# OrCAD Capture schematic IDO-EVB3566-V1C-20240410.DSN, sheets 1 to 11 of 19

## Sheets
1 P01. Revision History
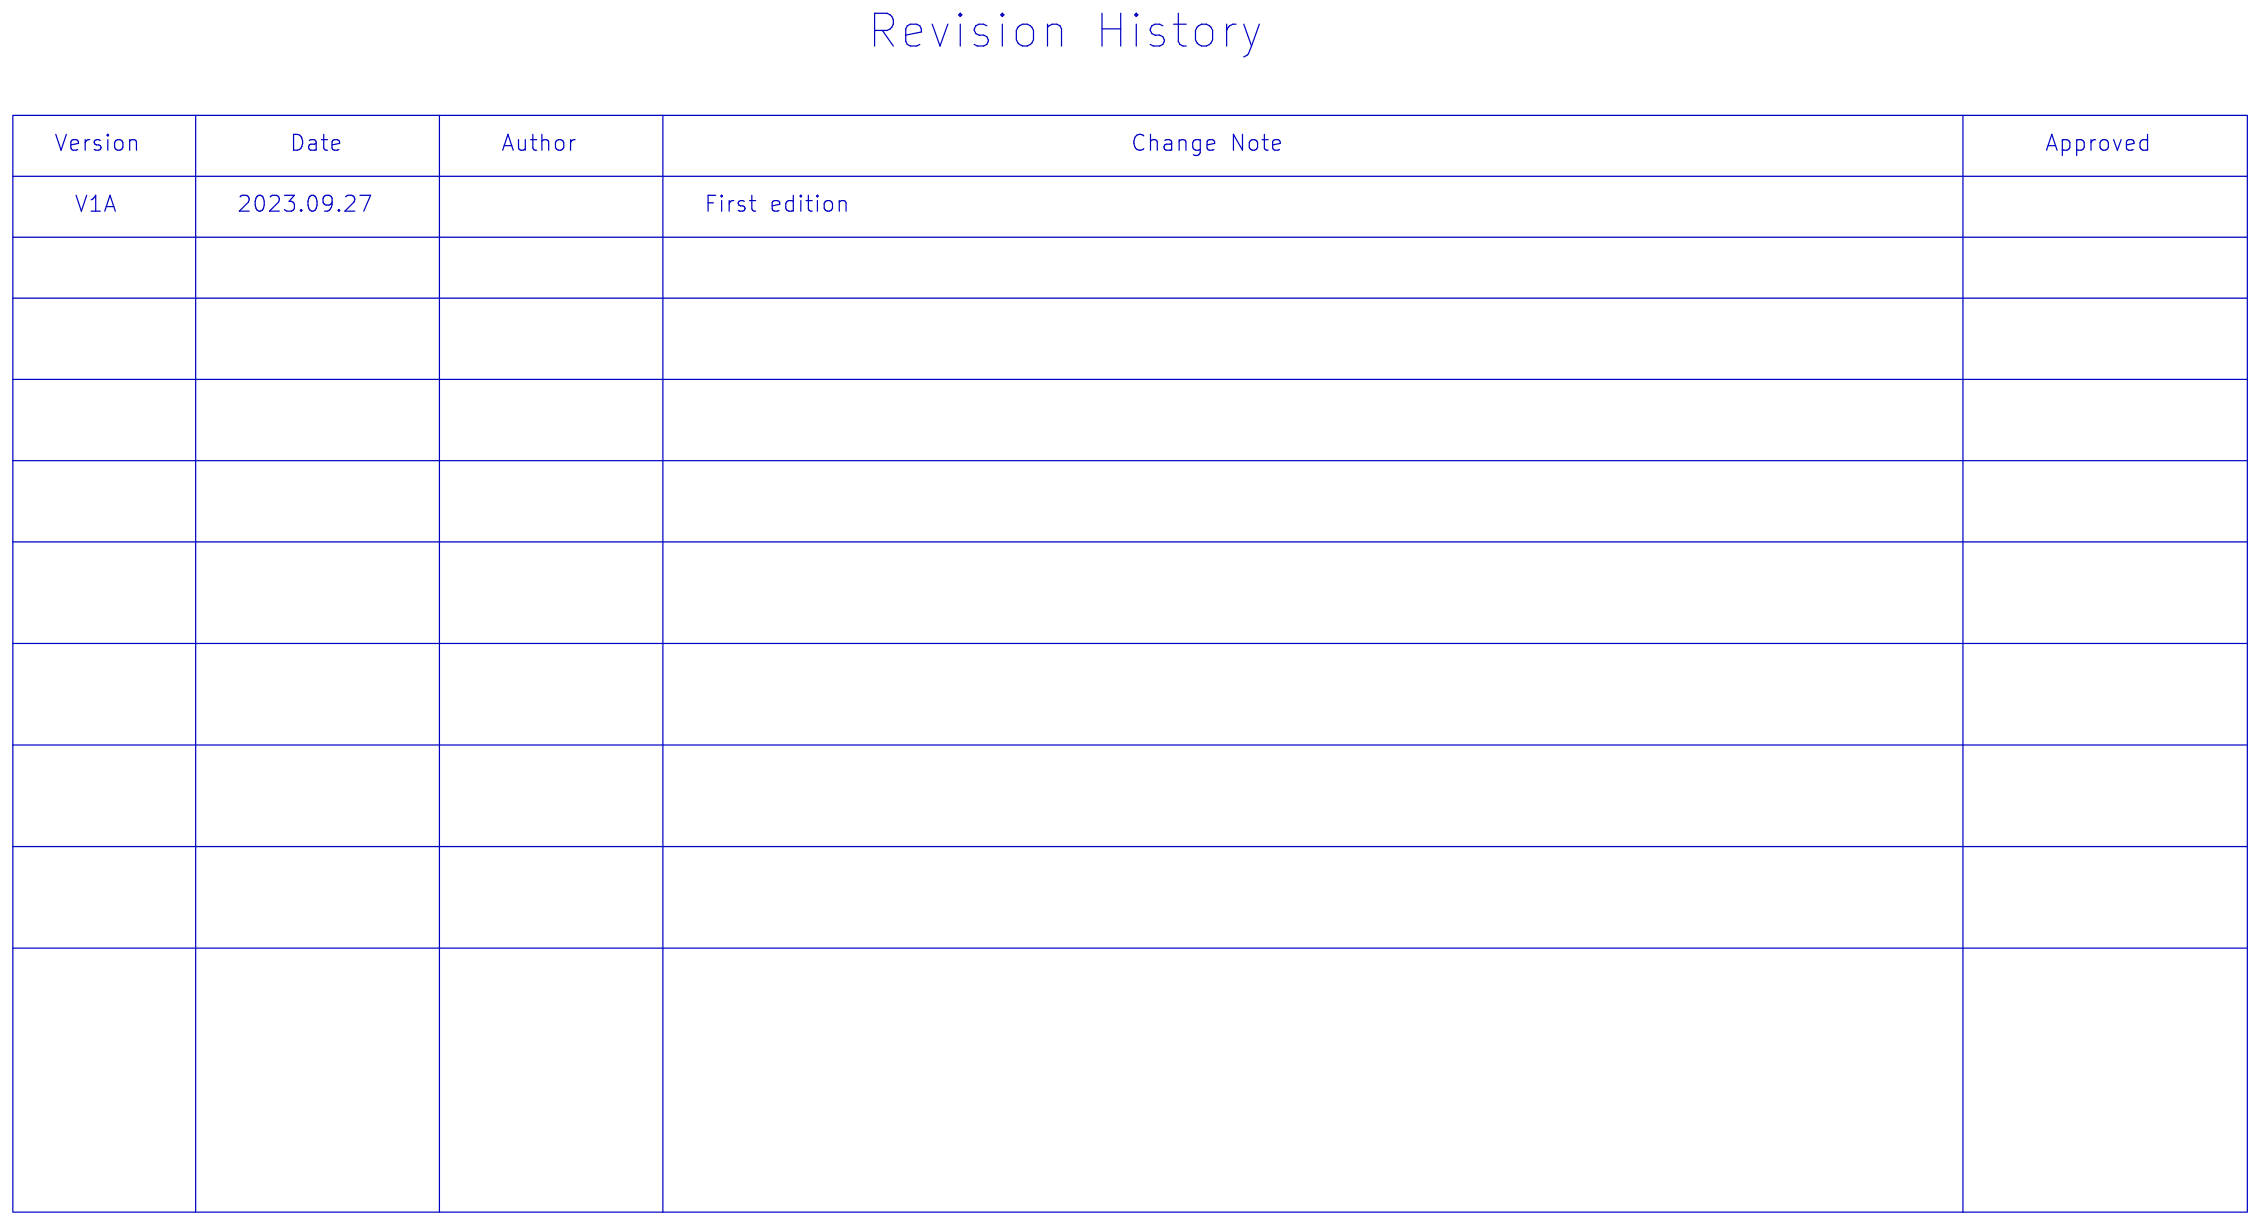
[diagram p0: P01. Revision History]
2 P02. Block_Diagram
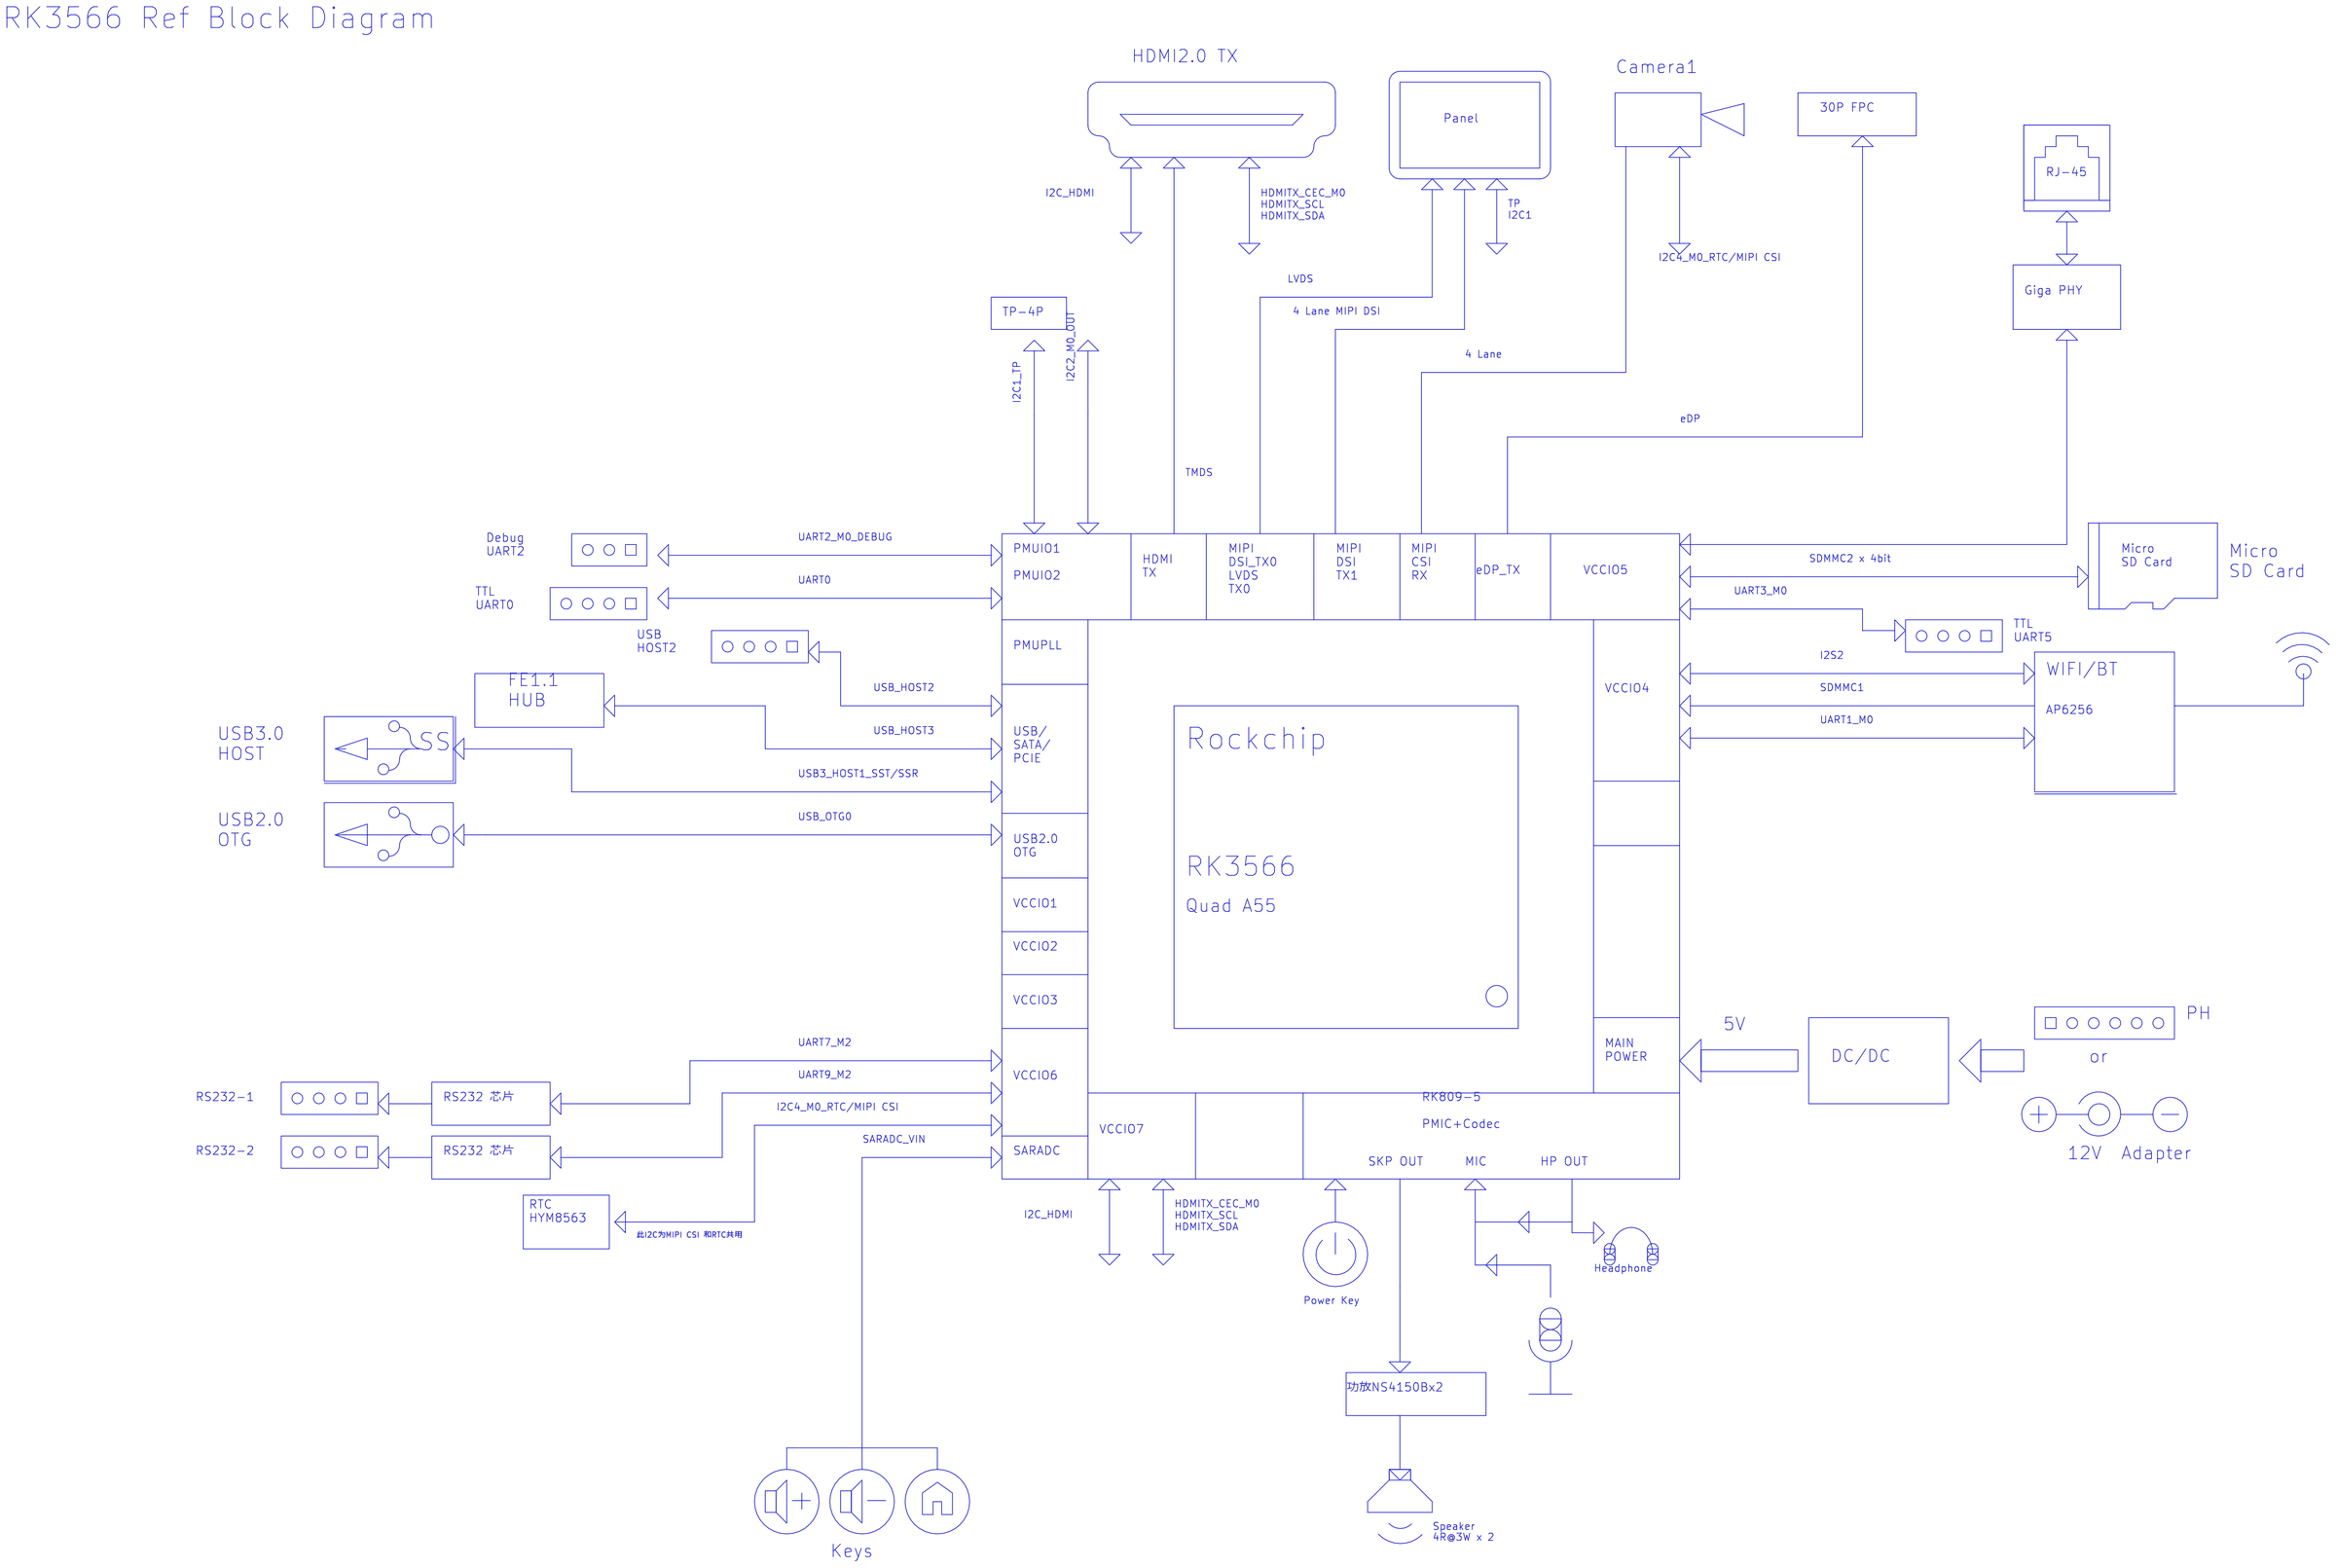
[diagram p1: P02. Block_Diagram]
3 P03. Power Diagram: title: IDO-EVB3568-V2; note: Power Diagram
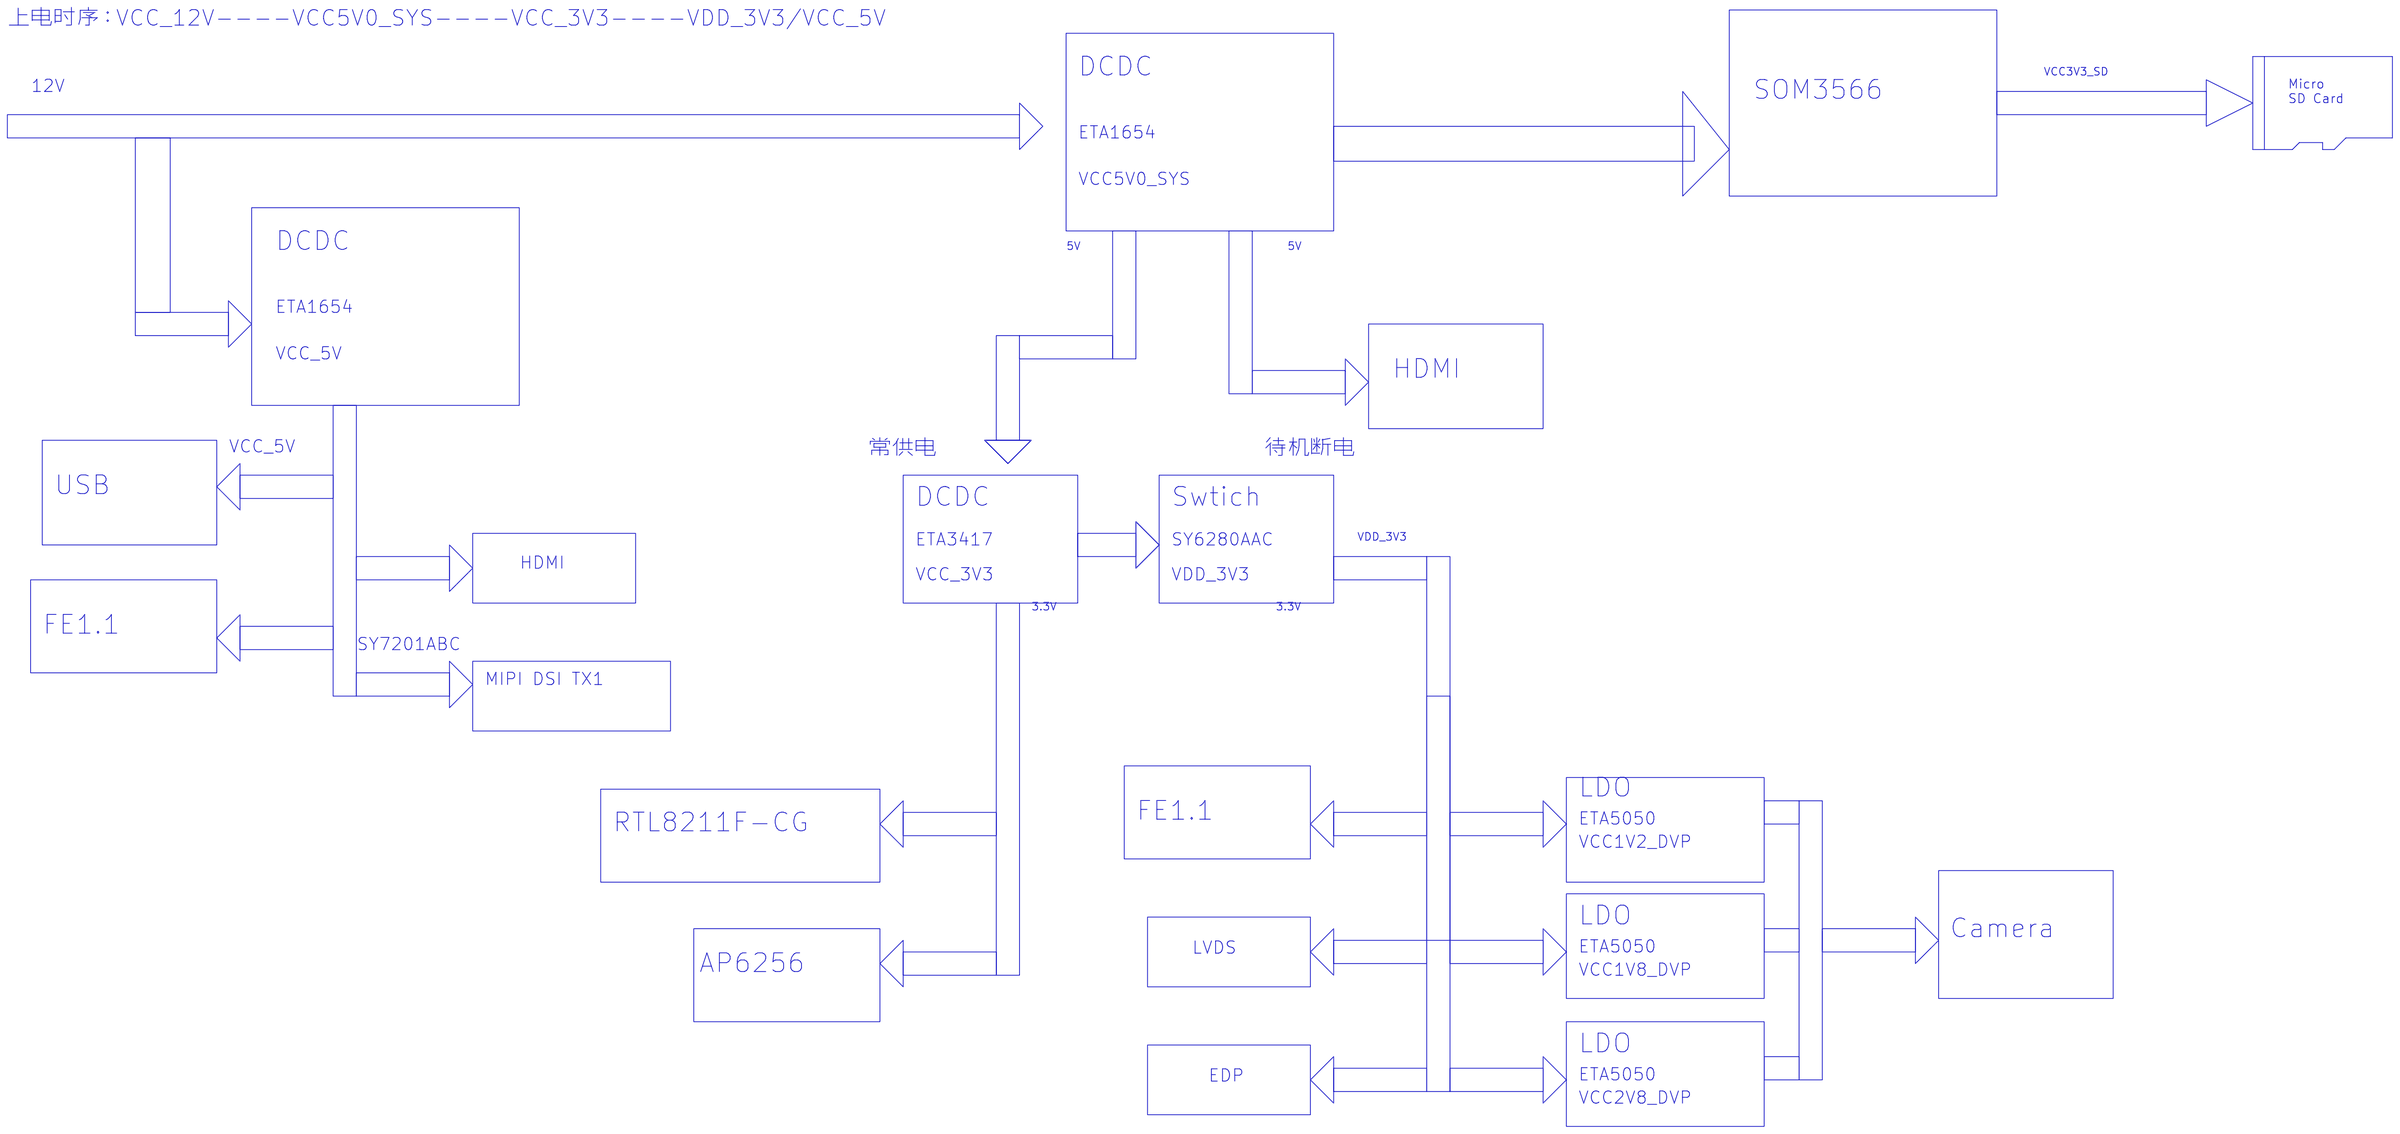
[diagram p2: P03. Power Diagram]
4 P05. SOM3566: size A2
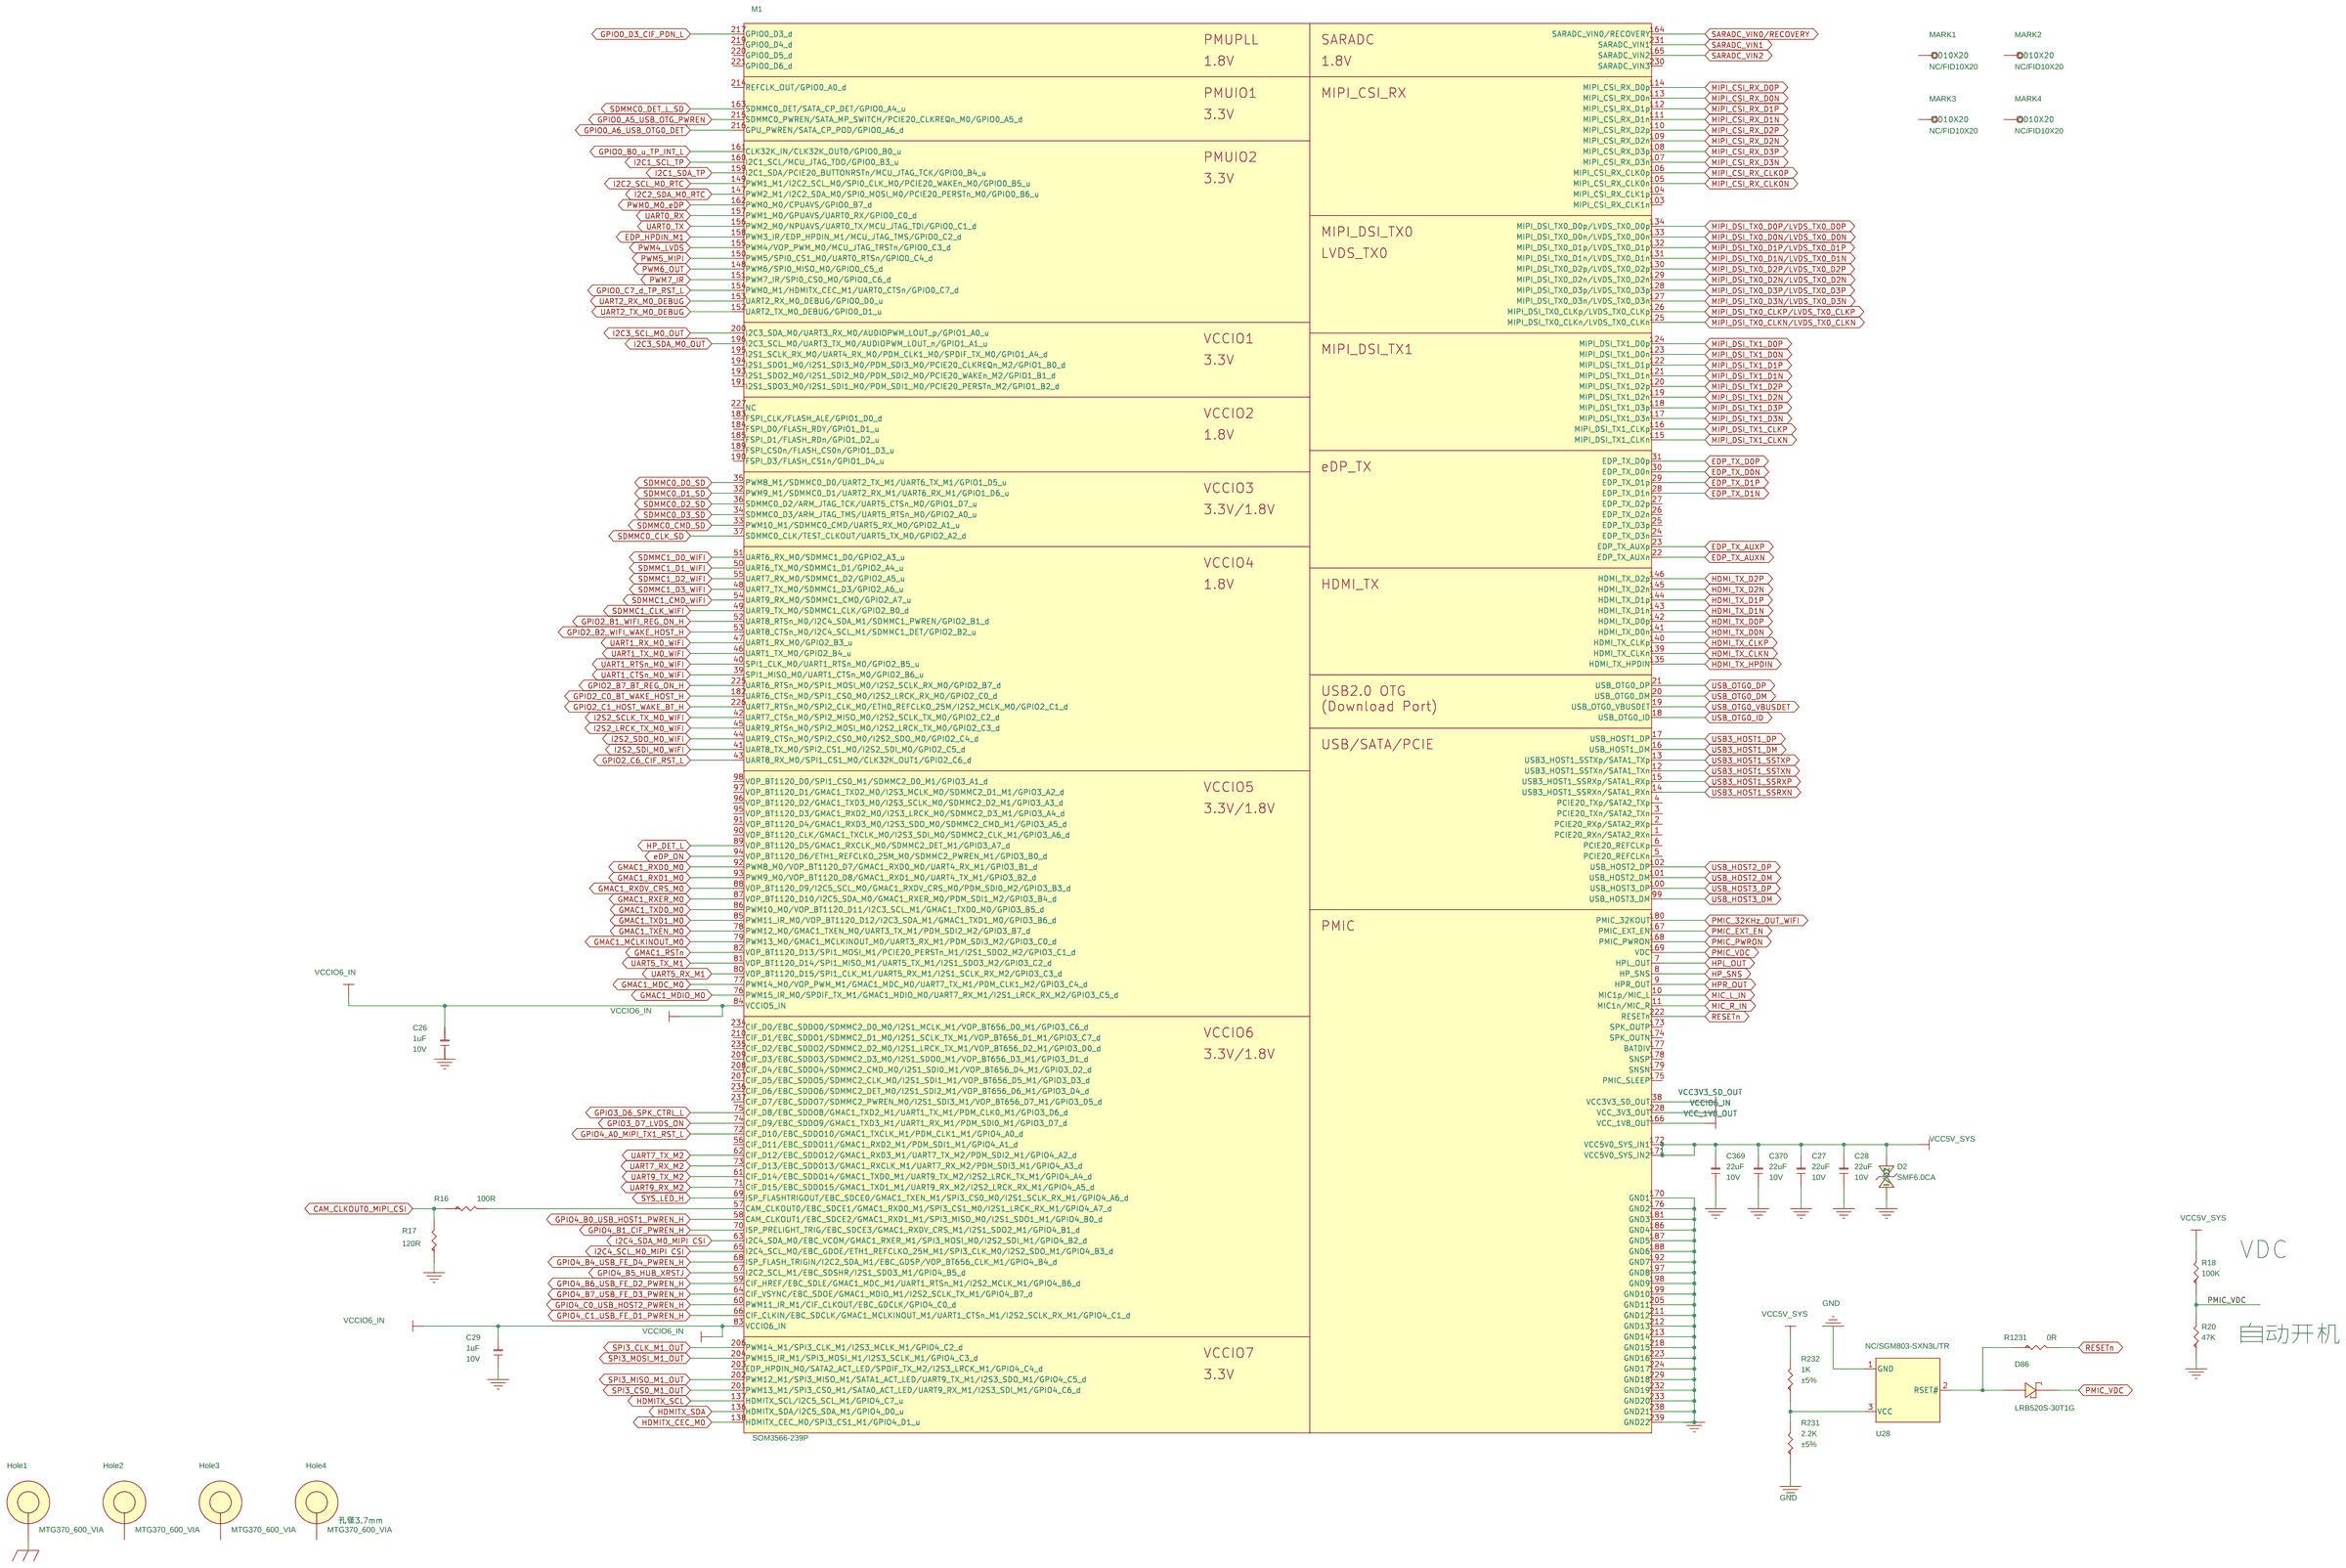
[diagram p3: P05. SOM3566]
5 P07. VO-eDP_TX: size A4; title: IDO-EVB3566-V1; note: VO-eDP Panel
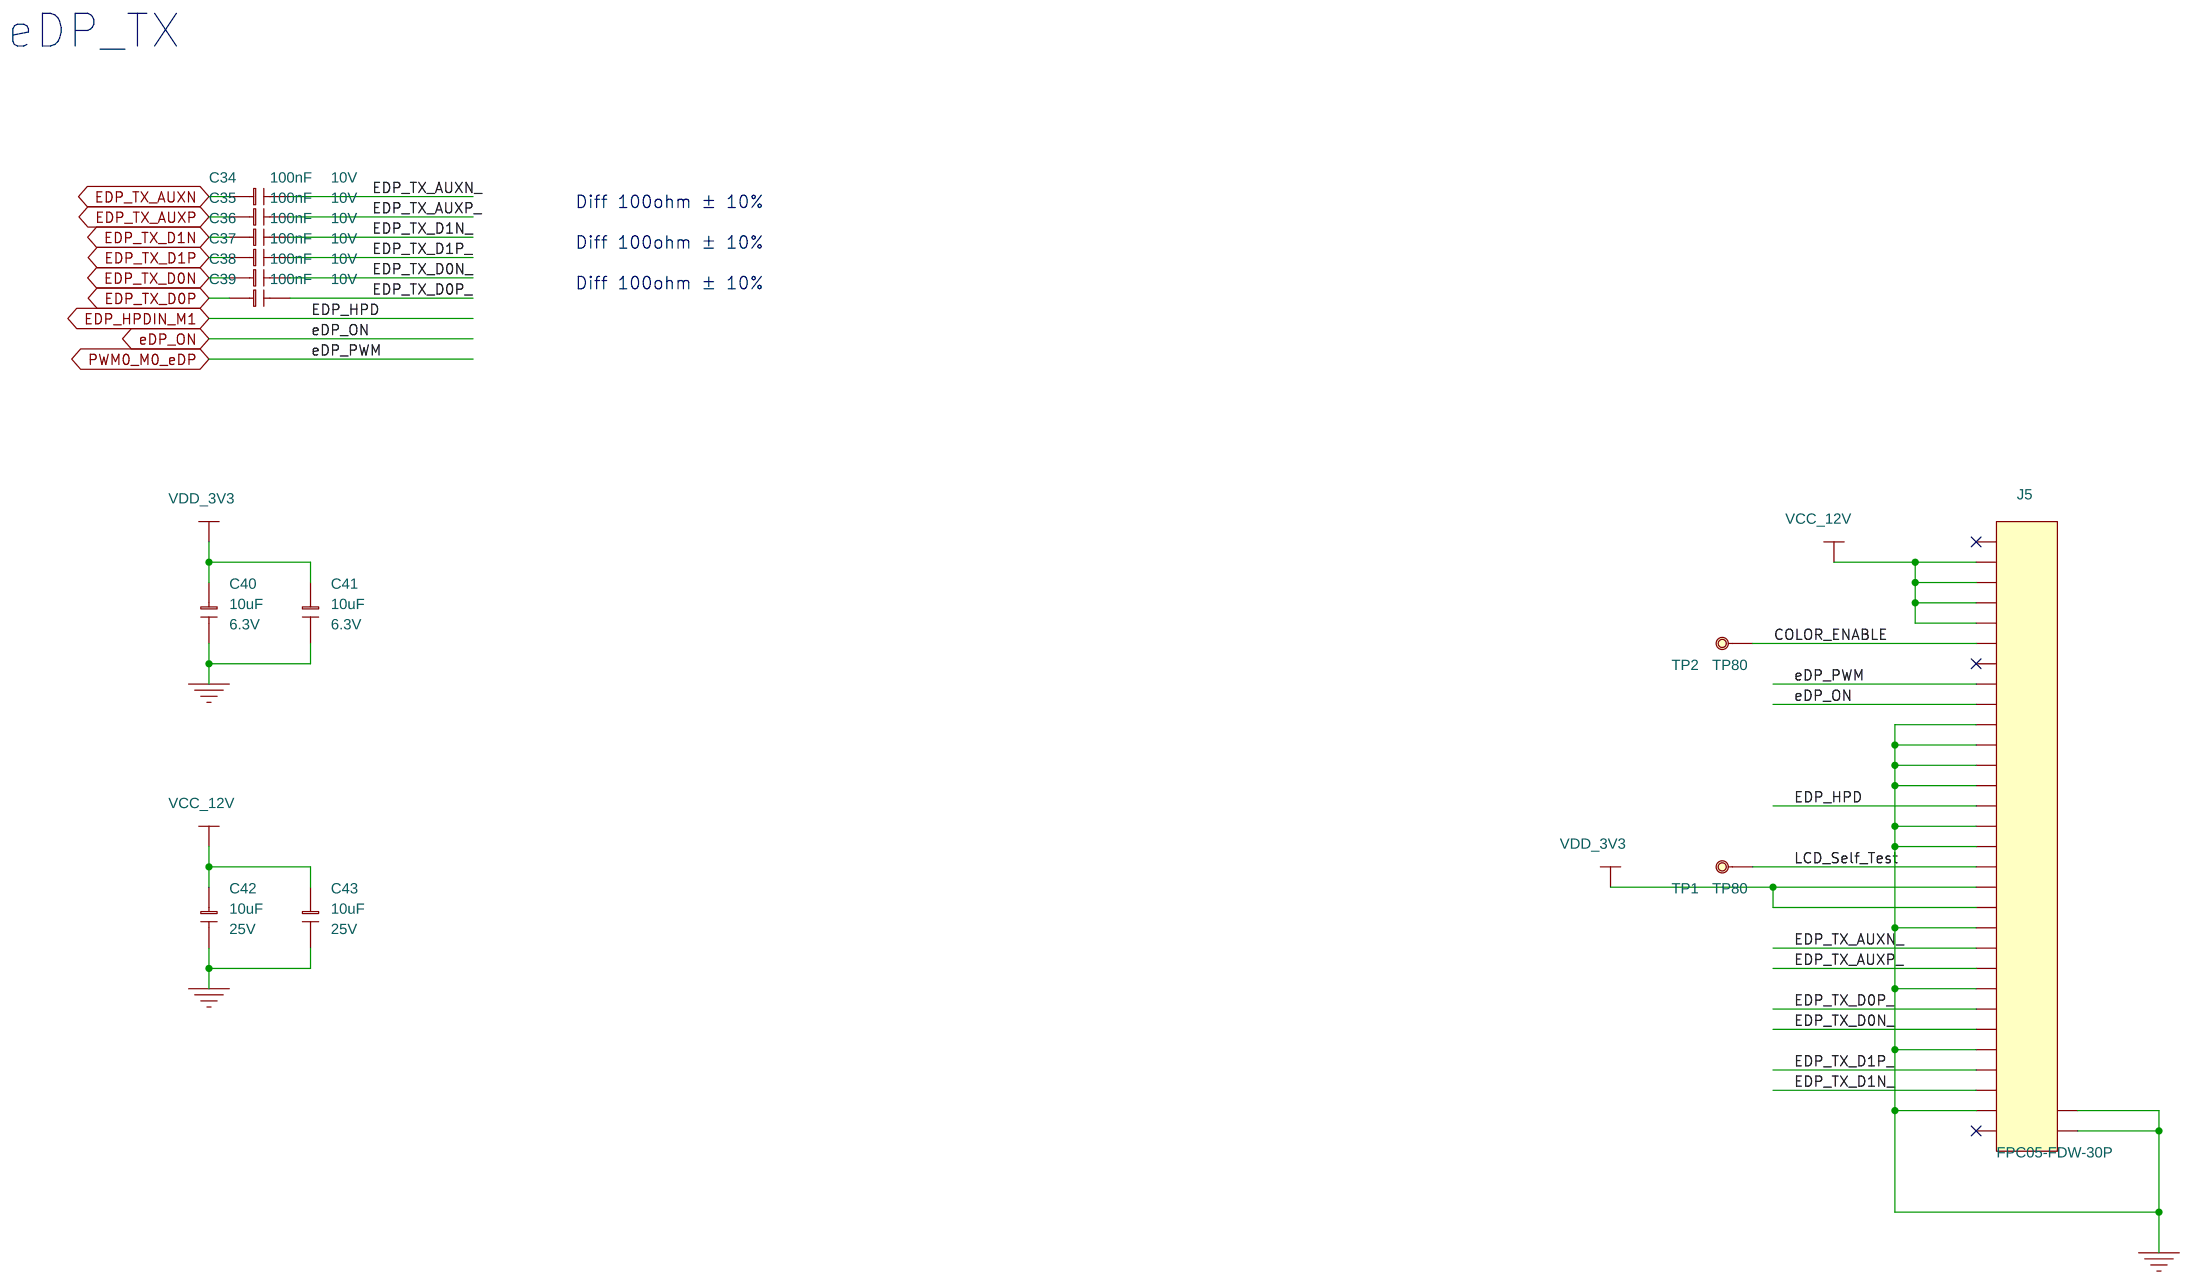
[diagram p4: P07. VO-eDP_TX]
6 P08. VO-HDMI2.0_TX: size A4
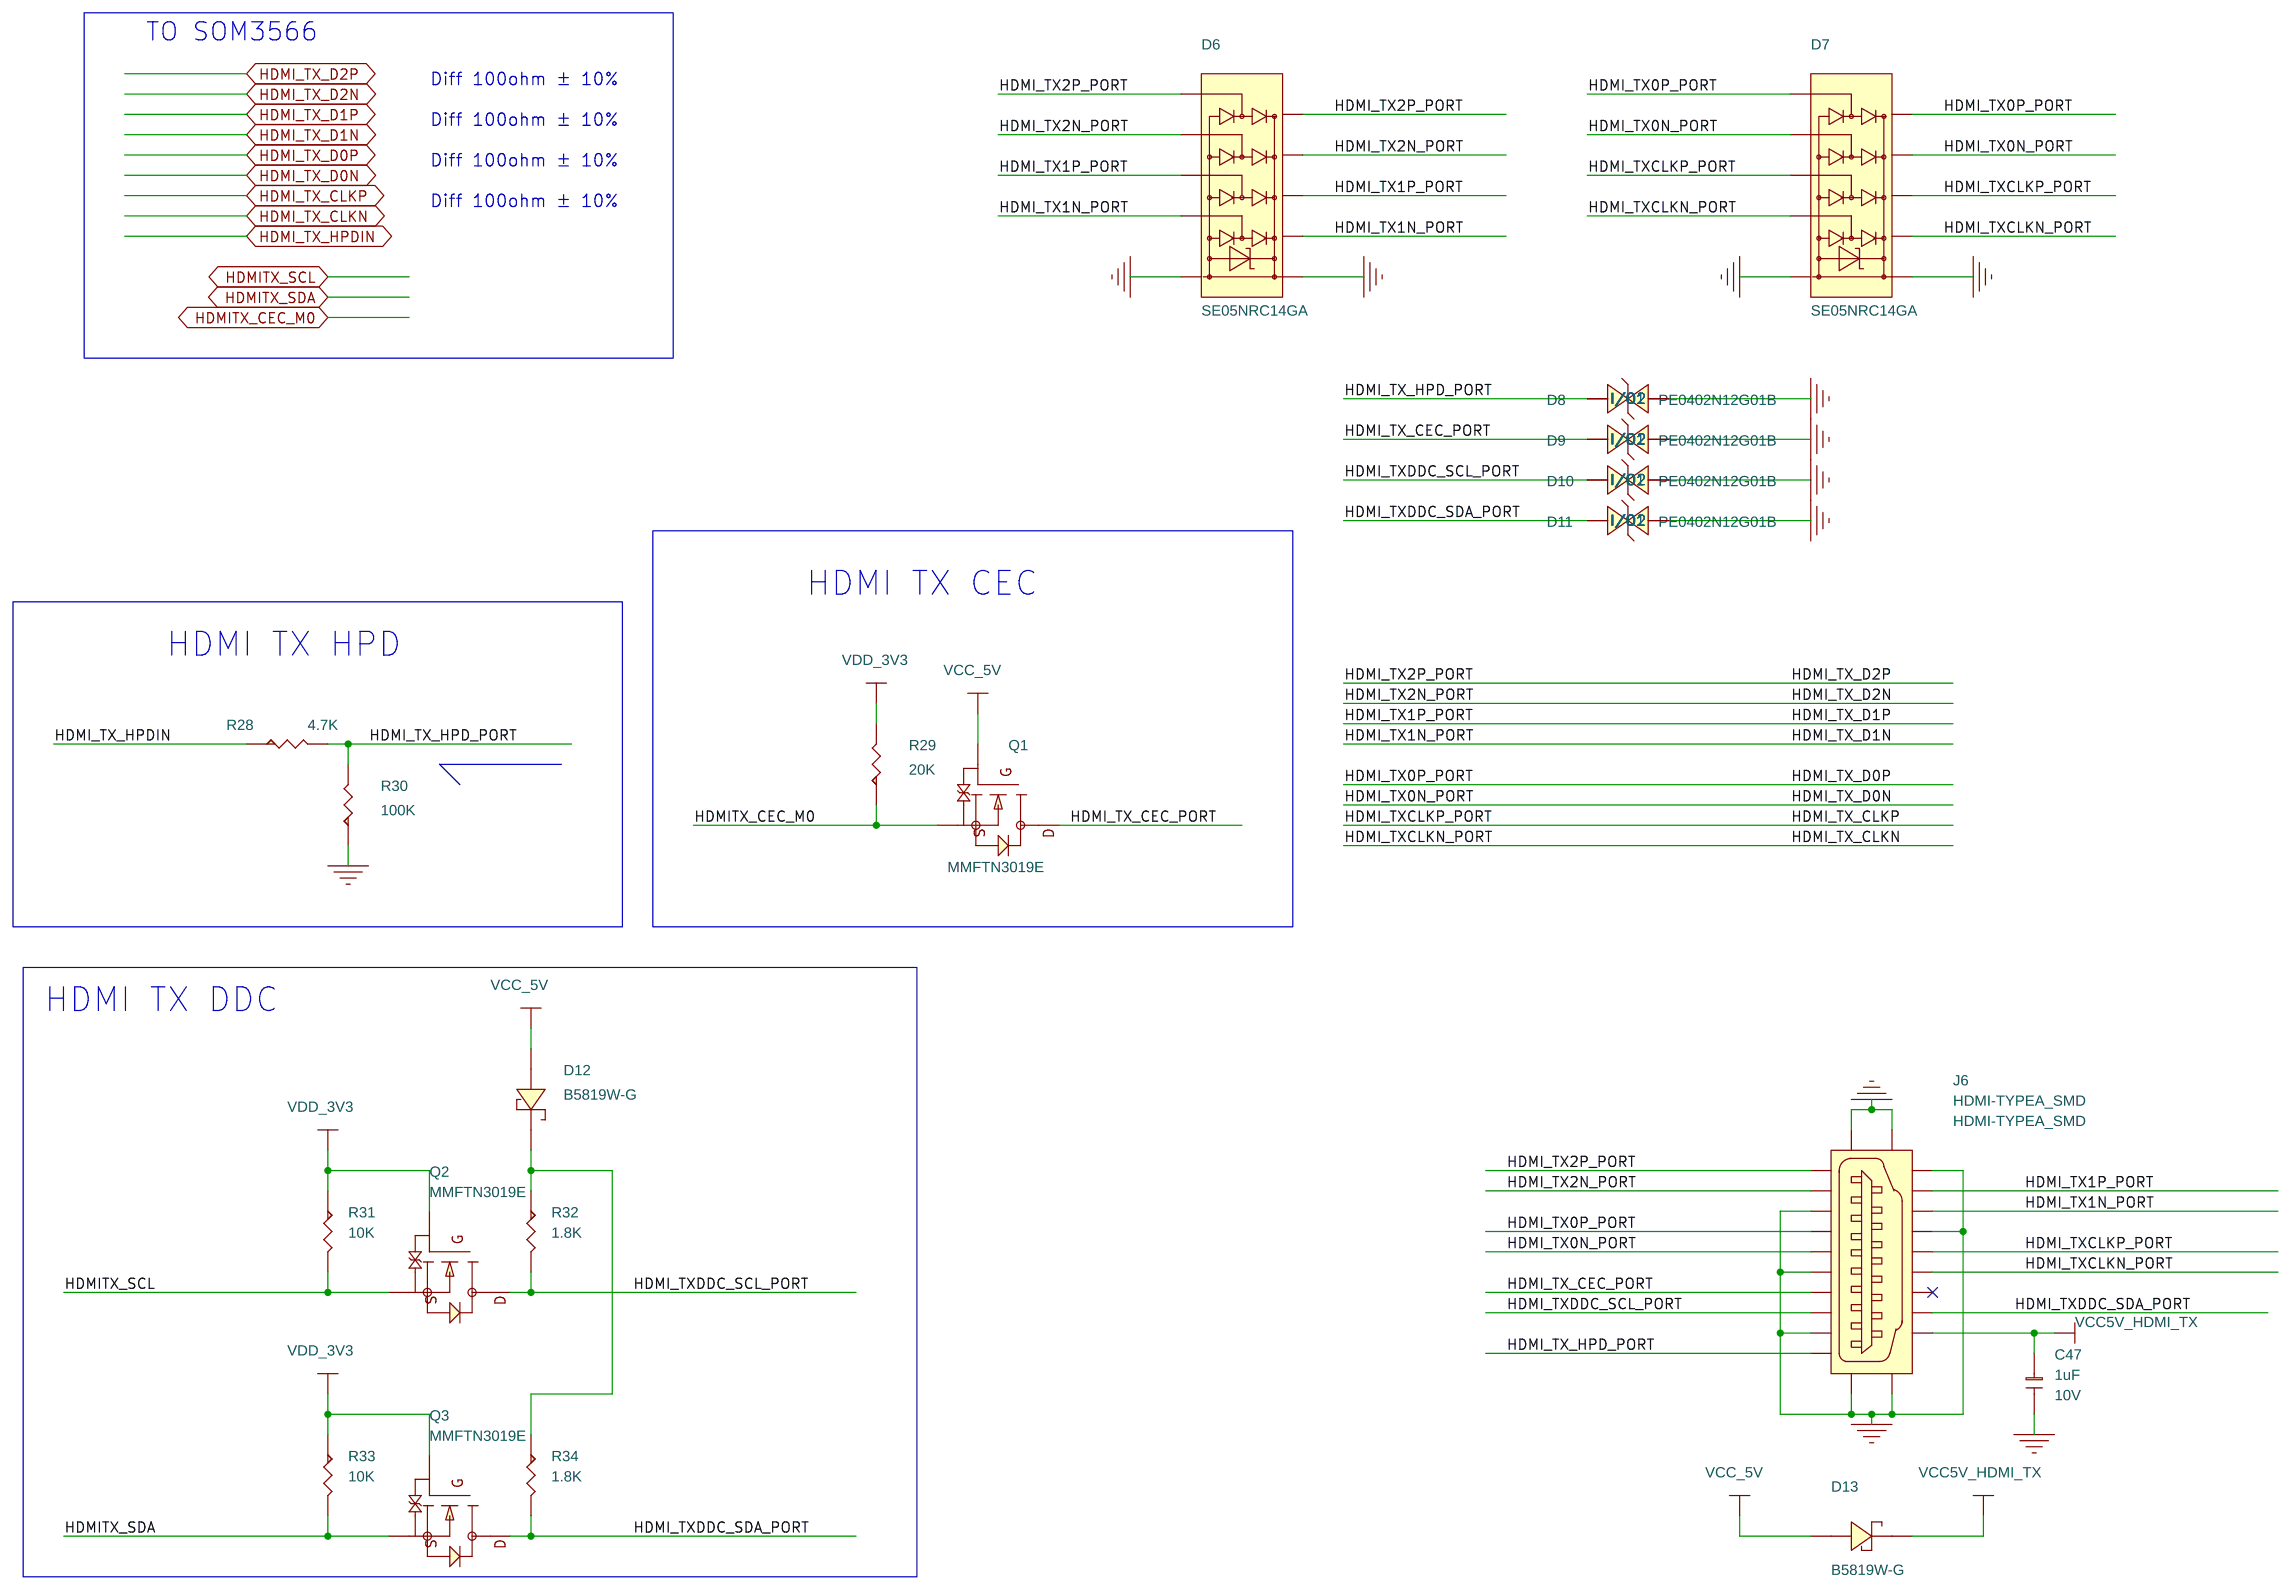
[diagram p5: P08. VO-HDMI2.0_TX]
7 P09. VO-LVDS: size A4
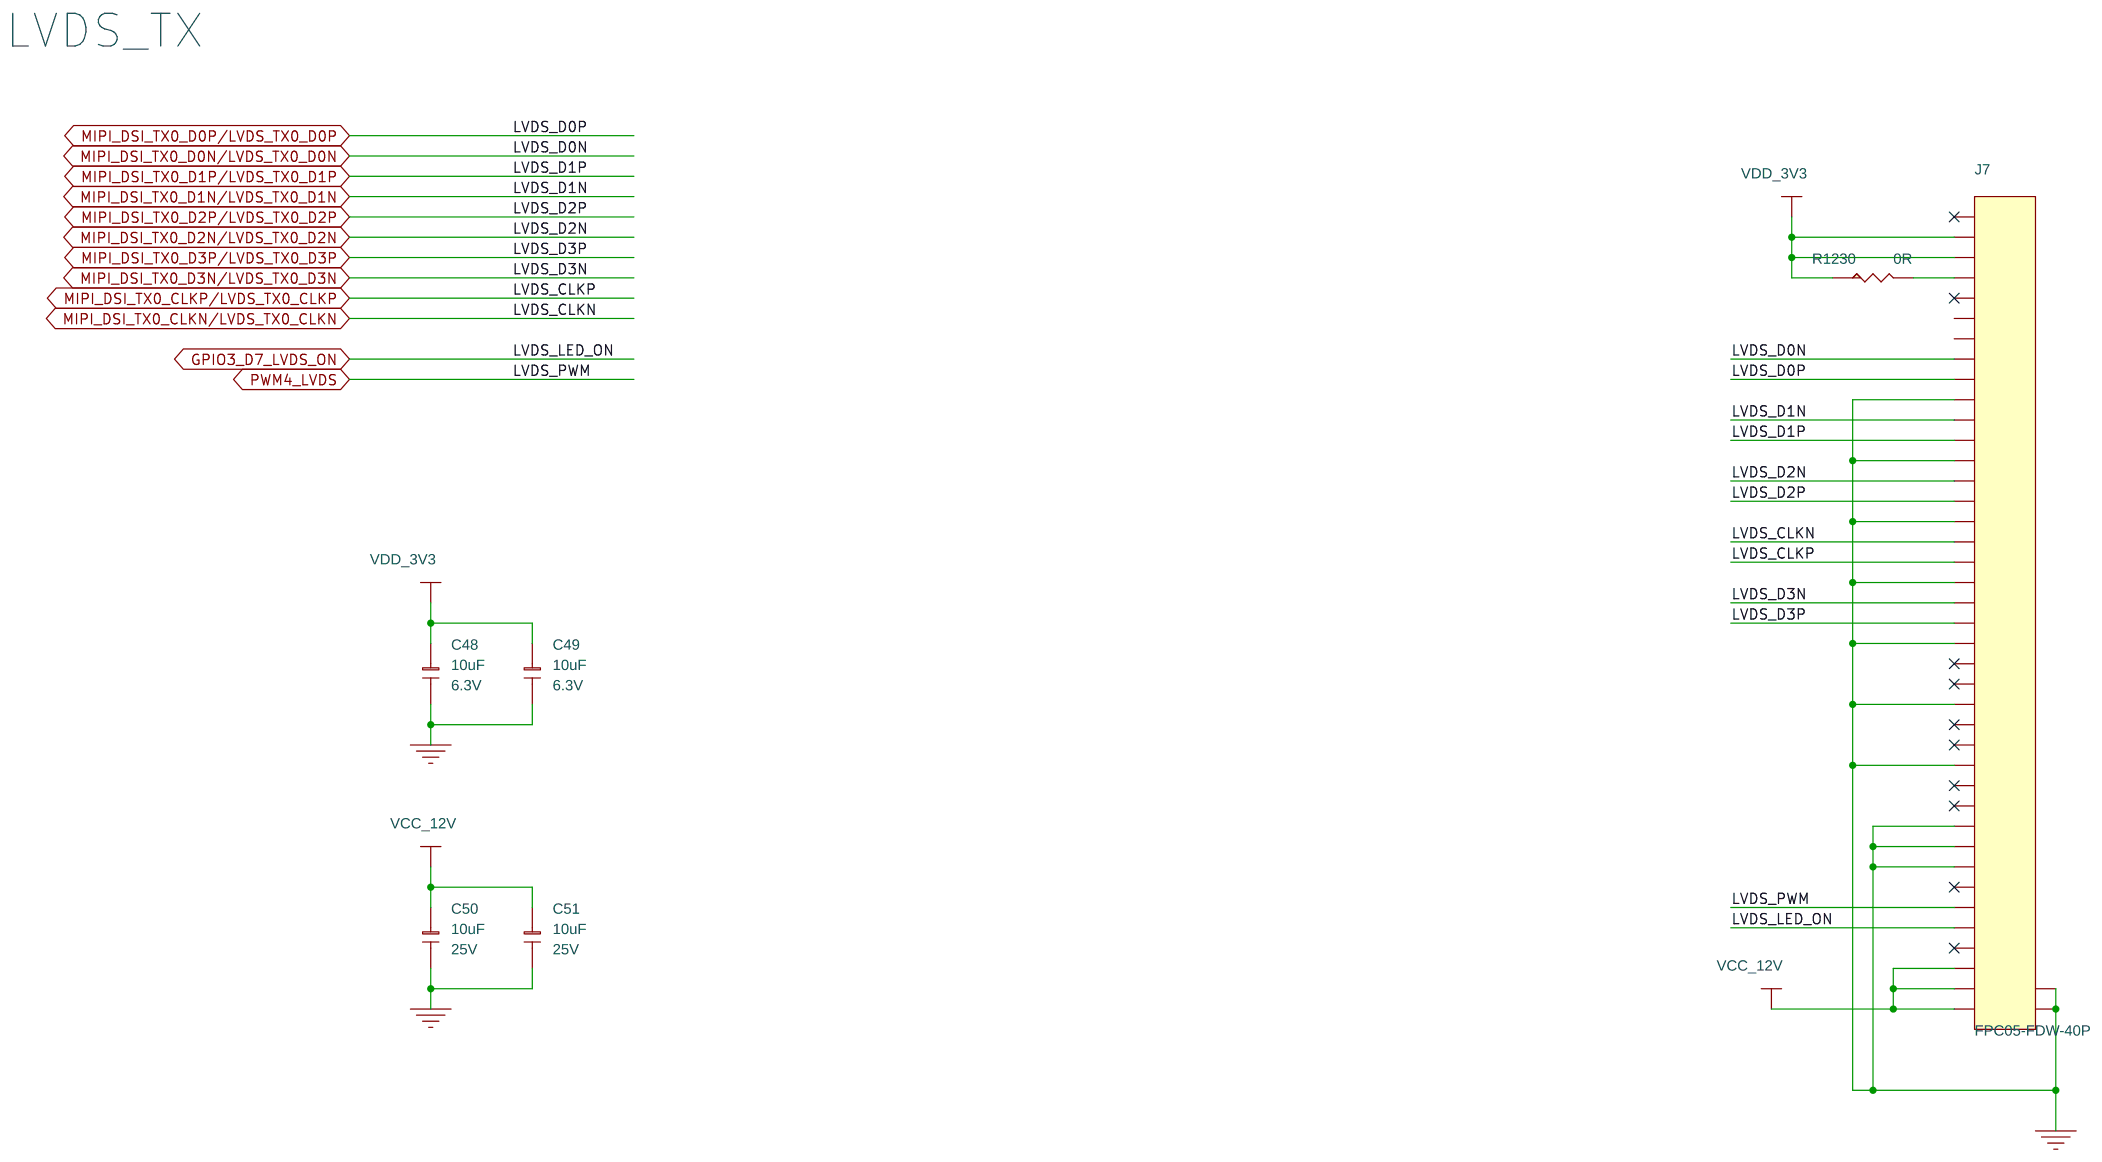
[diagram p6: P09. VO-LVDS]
8 P11. VI-Camera_MIPI_CSI: size A4
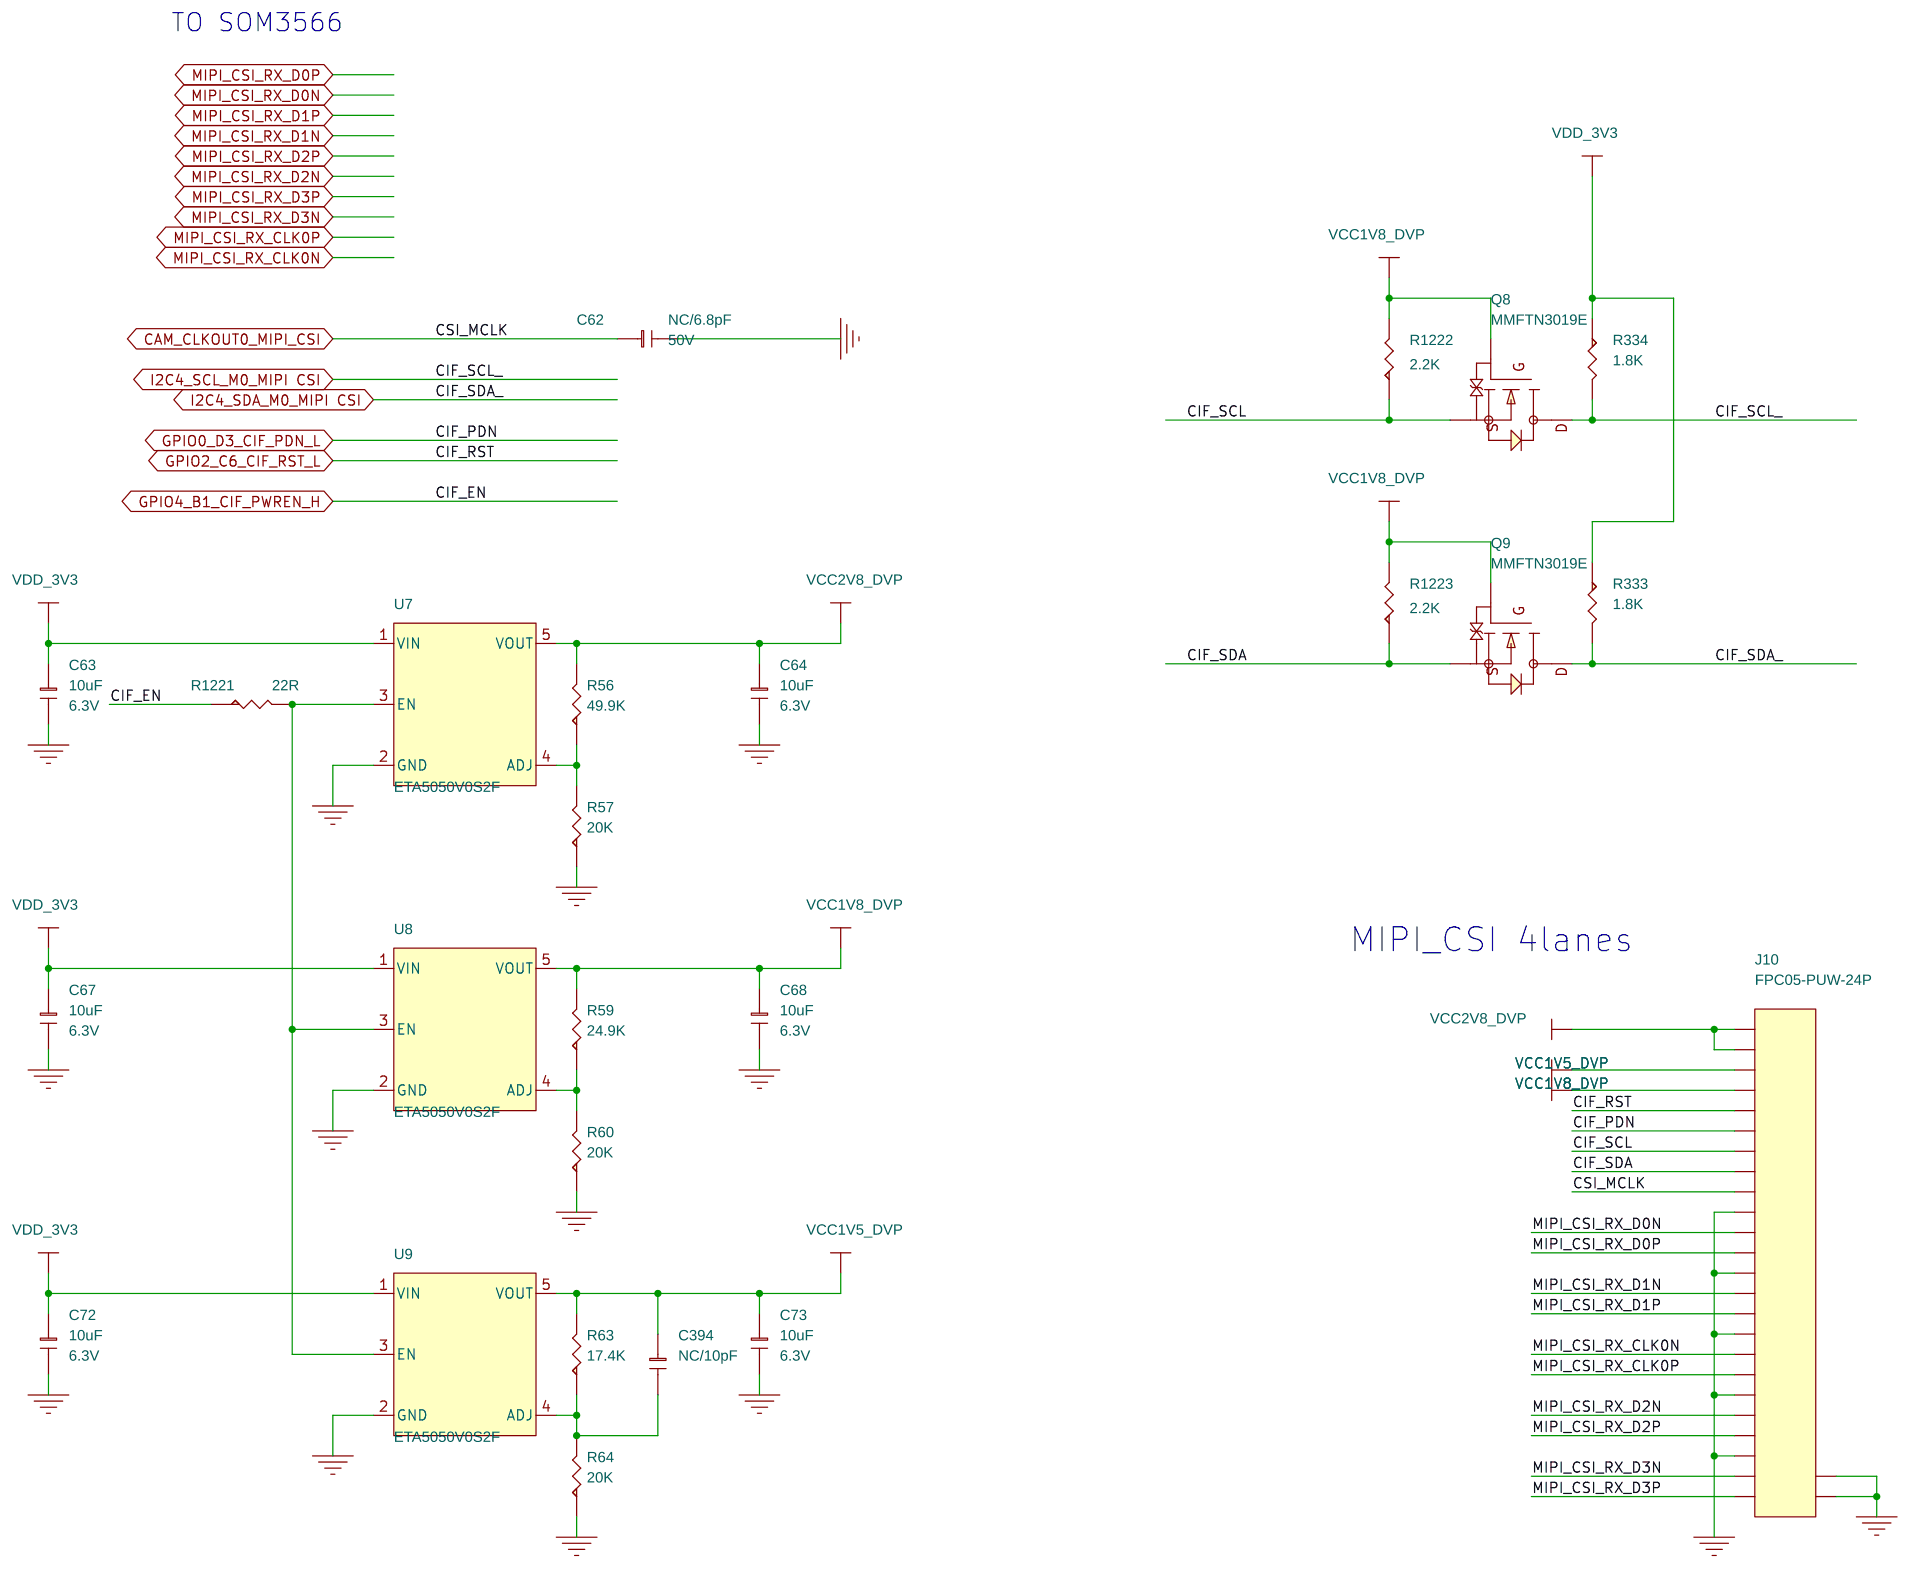
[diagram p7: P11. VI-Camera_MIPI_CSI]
9 P19. GPIO: size A
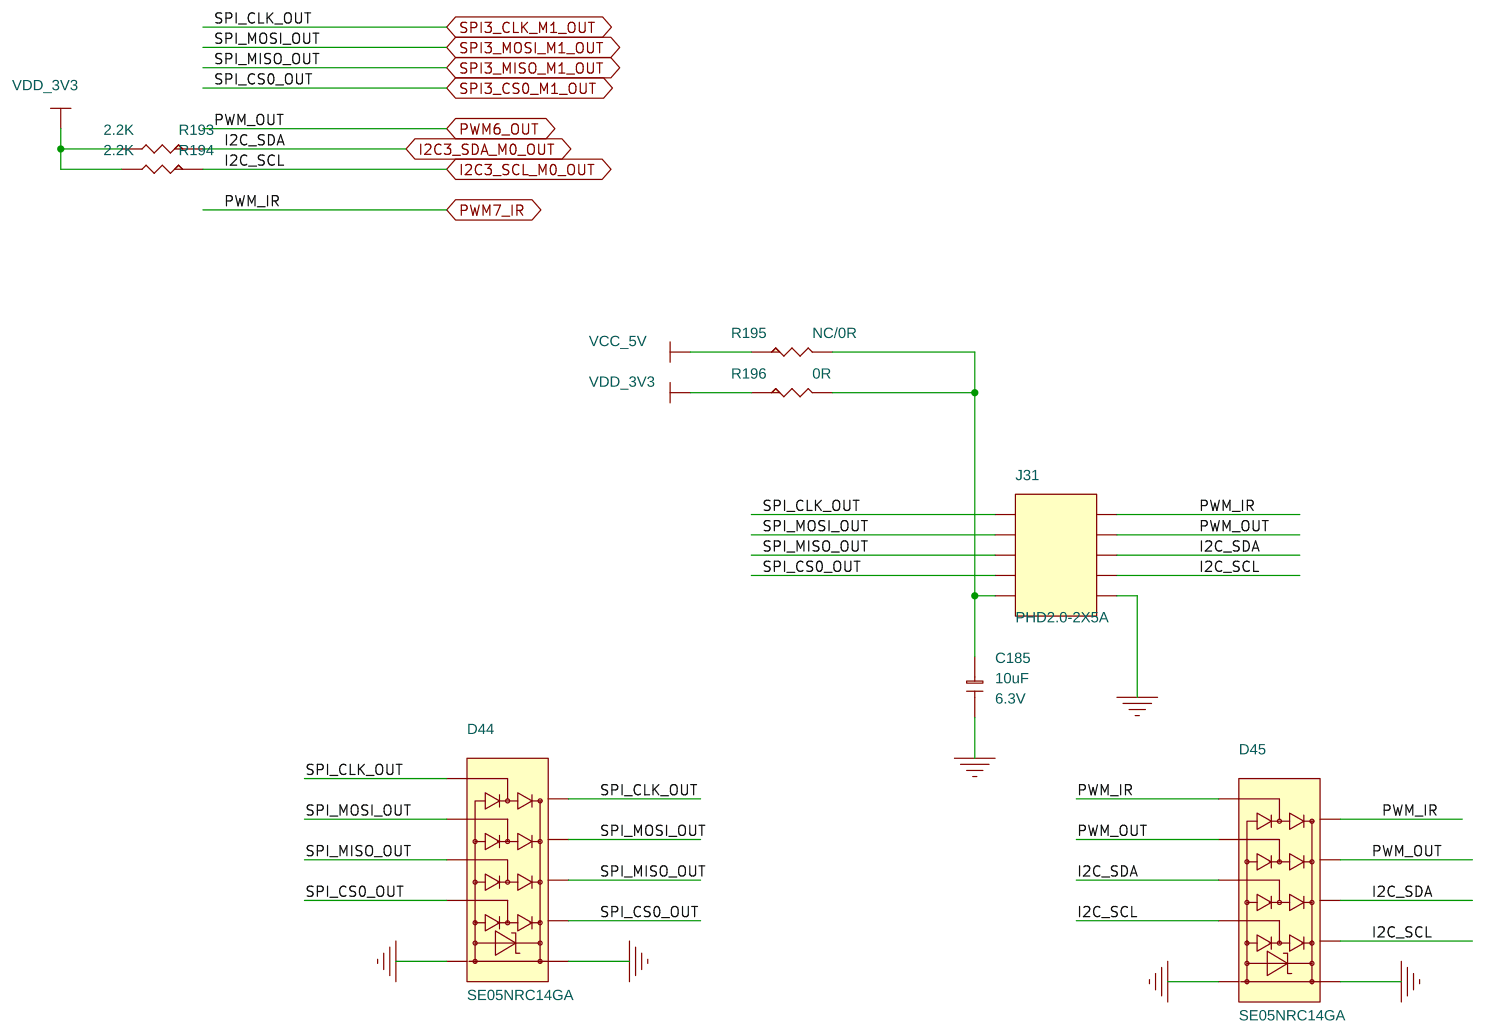
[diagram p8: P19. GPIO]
10 P17. 1MIC/2SPK/HP: size A4
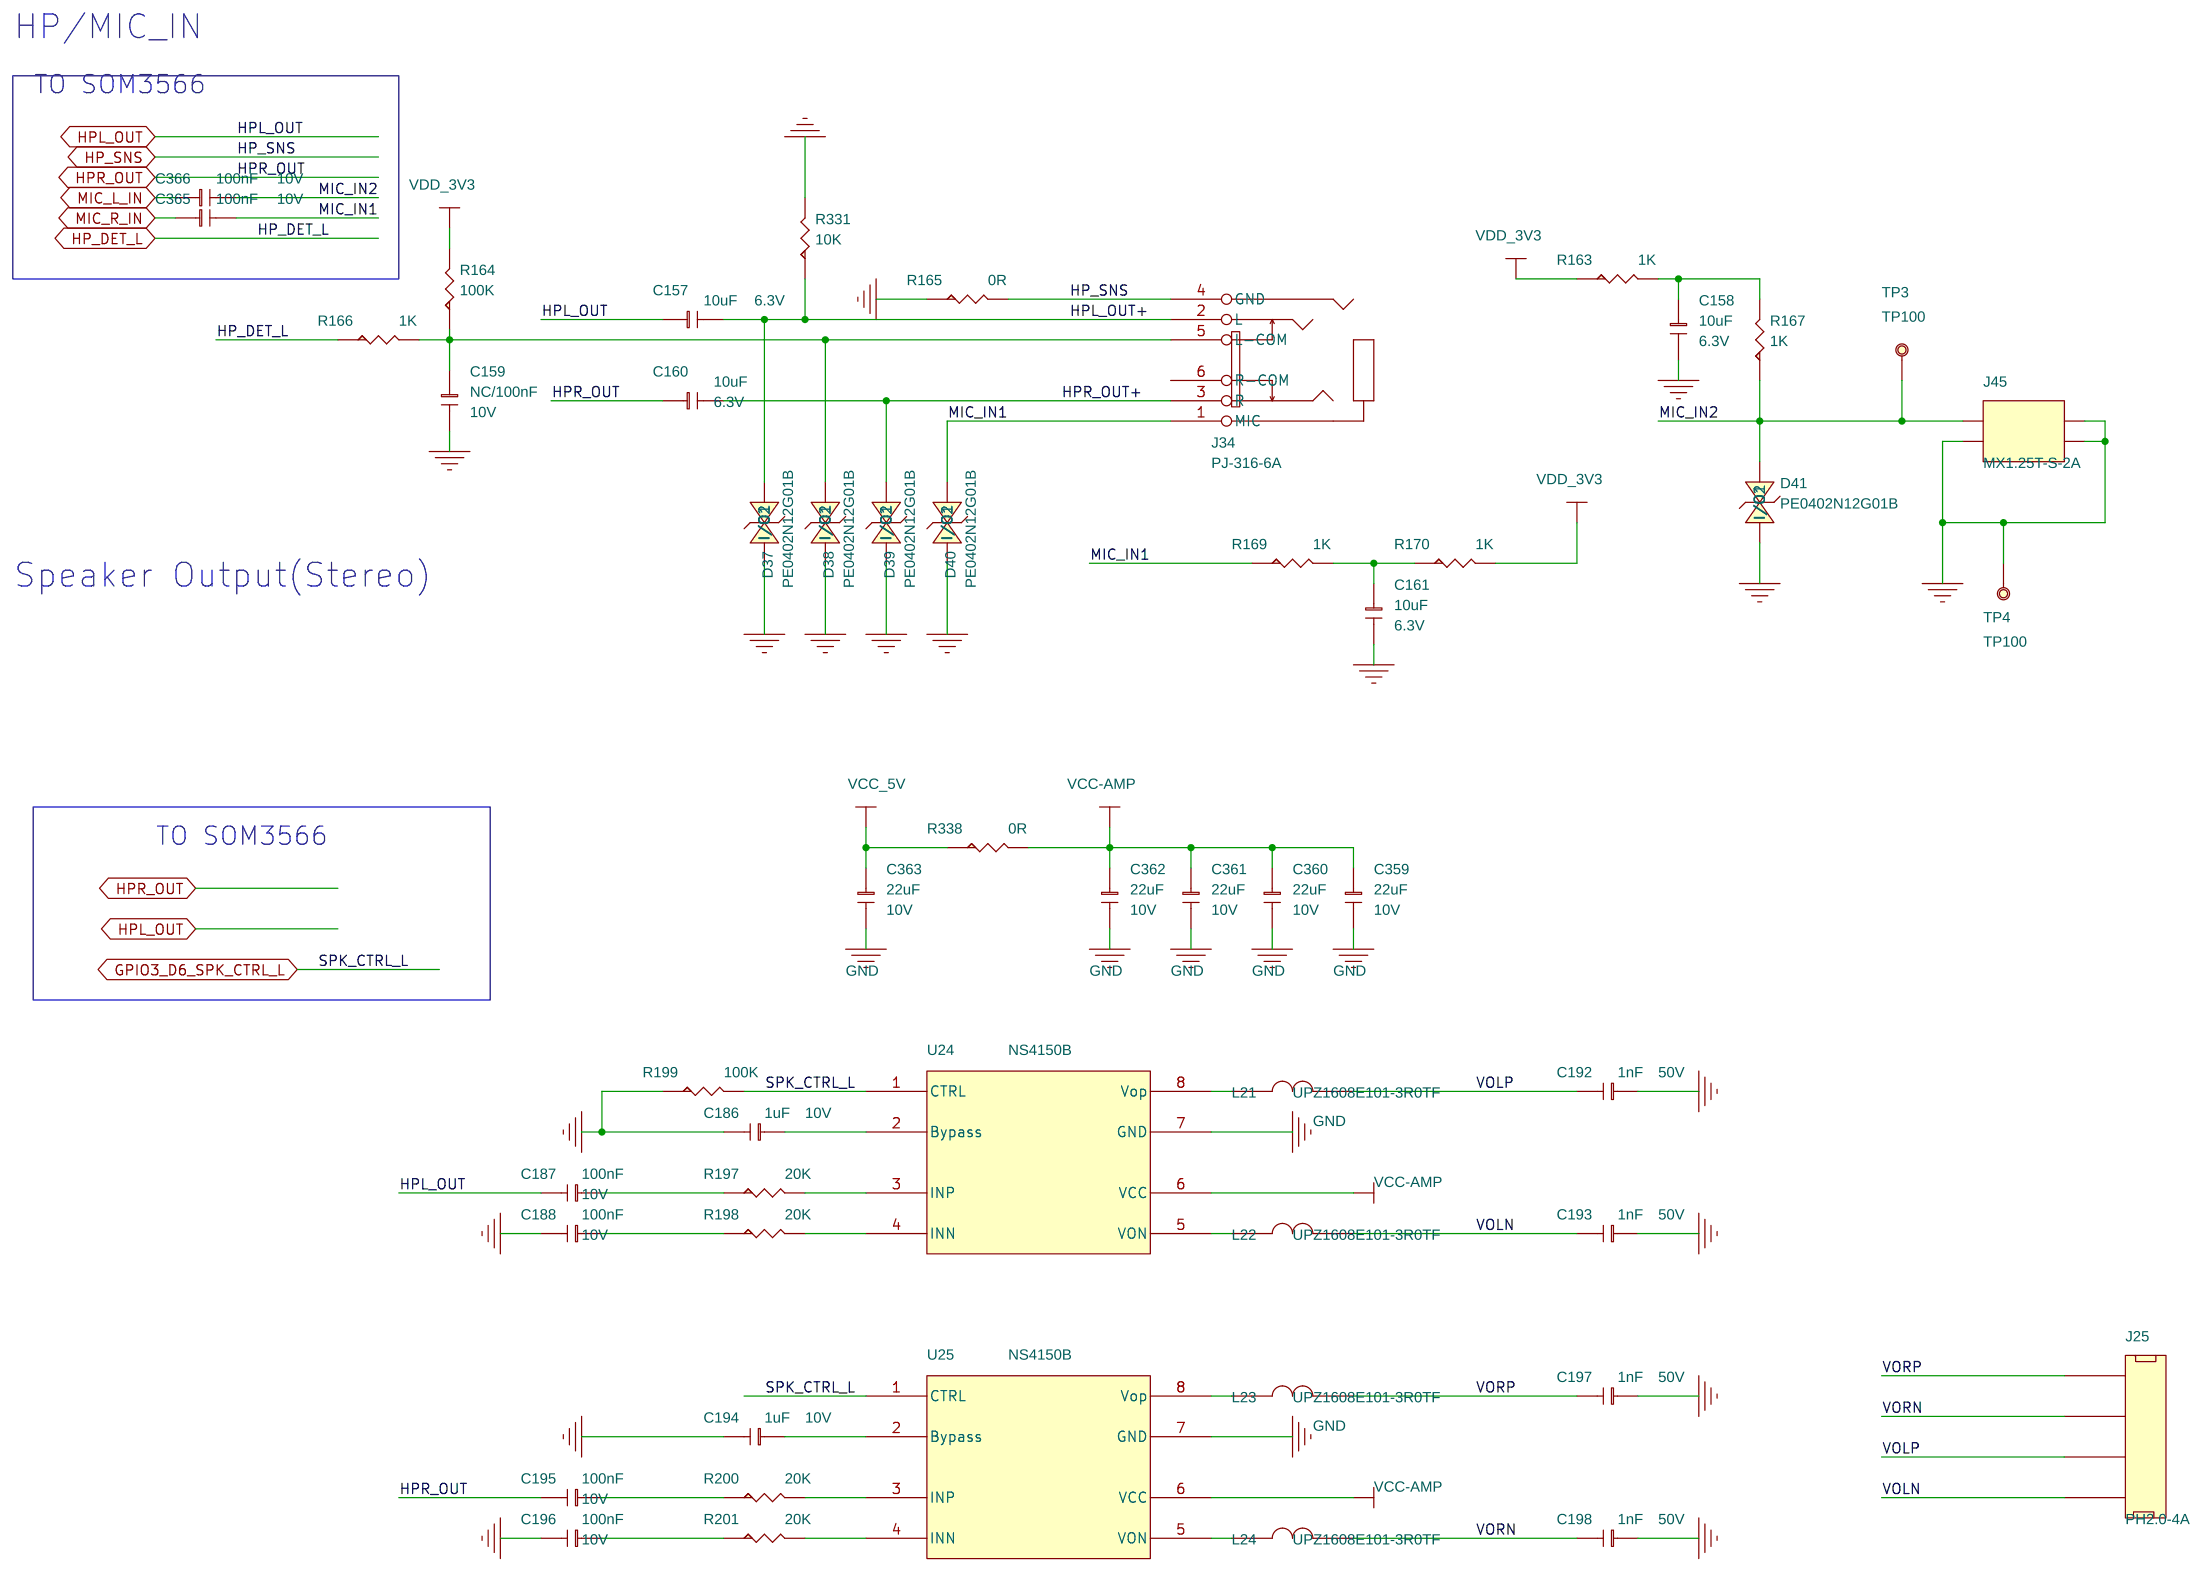
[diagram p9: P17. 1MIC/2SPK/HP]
11 P04. Power/LED: size A4
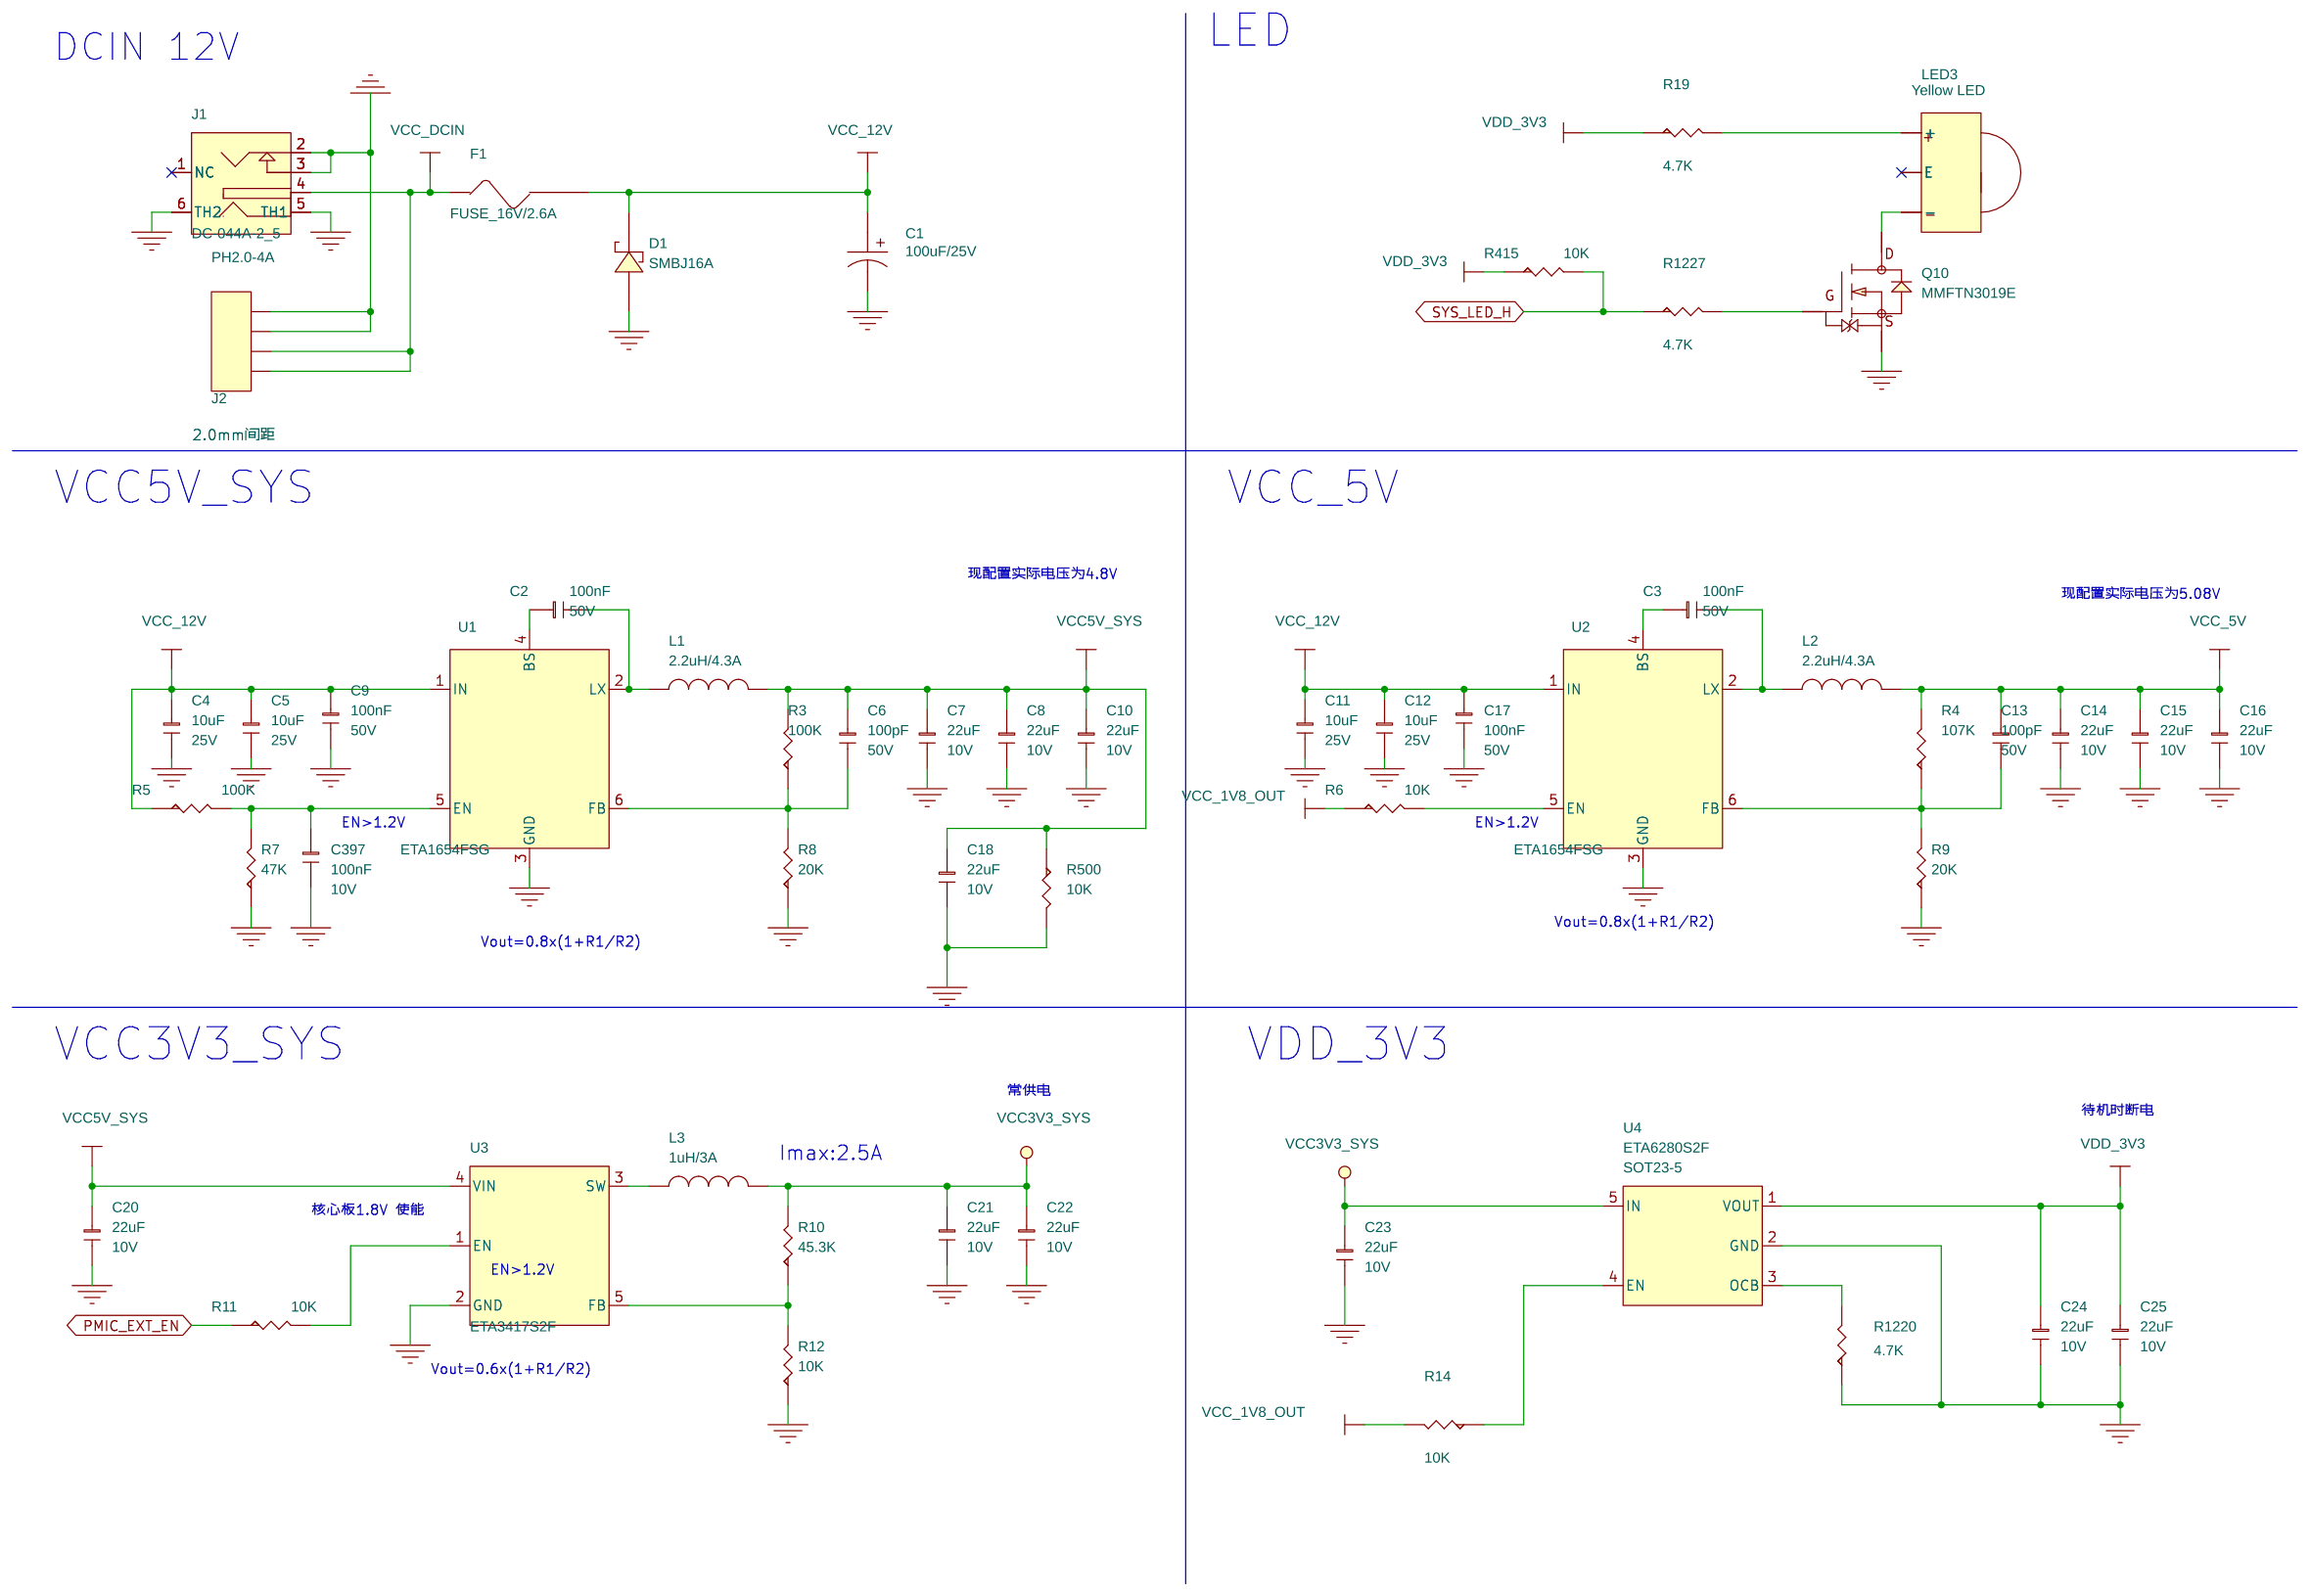
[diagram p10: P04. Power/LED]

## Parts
sheet P04. Power/LED
C1  100uF/25V  [CAPAE660X540]
C2  100nF  [C0402]
C3  100nF  [C0402]
C4  10uF  [C0805]
C5  10uF  [C0805]
C6  100pF  [C0402]
C7  22uF  [C0603]
C8  22uF  [C0603]
C9  100nF  [C0402]
C10  22uF  [C0603]
C11  10uF  [C0805]
C12  10uF  [C0805]
C13  100pF  [C0402]
C14  22uF  [C0603]
C15  22uF  [C0603]
C16  22uF  [C0603]
C17  100nF  [C0402]
C18  22uF  [C0603]
C20  22uF  [C0603]
C21  22uF  [C0603]
C22  22uF  [C0603]
C23  22uF  [C0603]
C24  22uF  [C0603]
C25  22uF  [C0603]
C397  100nF  [C0402]
D1  SMBJ16A  [SMB_DO-214AA]
F1  FUSE_16V/2.6A  [SMD1812]
J1  DC-044A-2_5  [DC-044A-2_0-DIP]
J2  PH2.0-4A  [PH200-4A]
L1  2.2uH/4.3A  [IND_404020]
L2  2.2uH/4.3A  [IND_404020]
L3  1uH/3A  [IND_252012]
LED3  Yellow LED  [LED-SMD_3_2X1_5X1_0]
Q10  MMFTN3019E  [SOT523]
R3  100K  [R0402]
R4  107K  [R0402]
R5  100K  [R0402]
R6  10K  [R0402]
R7  47K  [R0402]
R8  20K  [R0402]
R9  20K  [R0402]
R10  45.3K  [R0402]
R11  10K  [R0402]
R12  10K  [R0402]
R14  10K  [R0402]
R19  4.7K  [R0402]
R415  10K  [R0402]
R500  10K  [R0402]
R1220  4.7K  [R0402]
R1227  4.7K  [R0402]
U1  ETA1654FSG  [SOT563]
U2  ETA1654FSG  [SOT563]
U3  ETA3417S2F  [SOT23-5]
U4  ETA6280S2F  [SOT23-5]
sheet P05. SOM3566
C26  1uF  [C0402]
C27  22uF  [C0603]
C28  22uF  [C0603]
C29  1uF  [C0402]
C369  22uF  [C0603]
C370  22uF  [C0603]
D2  SMF6.0CA  [SOD-123F]
D86  LRB520S-30T1G  [SOD523]
Hole1  MTG370_600_VIA  [MTG370_600_VIA]
Hole2  MTG370_600_VIA  [MTG370_600_VIA]
Hole3  MTG370_600_VIA  [MTG370_600_VIA]
Hole4  MTG370_600_VIA  [MTG370_600_VIA]
M1  SOM3566-239P  [SOM3566-239P]
MARK1  NC/FID10X20  [FID10X20]
MARK2  NC/FID10X20  [FID10X20]
MARK3  NC/FID10X20  [FID10X20]
MARK4  NC/FID10X20  [FID10X20]
R16  100R  [R0402]
R17  120R  [R0402]
R18  100K  [R0402]
R20  47K  [R0402]
R231  2.2K  [R0402]
R232  1K  [R0402]
R1231  0R  [R0402]
U28  NC/SGM803-SXN3L/TR  [SOT23]
sheet P07. VO-eDP_TX
C34  100nF  [C0402]
C35  100nF  [C0402]
C36  100nF  [C0402]
C37  100nF  [C0402]
C38  100nF  [C0402]
C39  100nF  [C0402]
C40  10uF  [C0402]
C41  10uF  [C0402]
C42  10uF  [C0805]
C43  10uF  [C0805]
J5  FPC05-FDW-30P  [FPC05-30P]
TP1  TP80  [TP80]
TP2  TP80  [TP80]
sheet P08. VO-HDMI2.0_TX
C47  1uF  [C0402]
D6  SE05NRC14GA  [DFN2510-10L]
D7  SE05NRC14GA  [DFN2510-10L]
D8  PE0402N12G01B  [V0402]
D9  PE0402N12G01B  [V0402]
D10  PE0402N12G01B  [V0402]
D11  PE0402N12G01B  [V0402]
D12  B5819W-G  [SOD123]
D13  B5819W-G  [SOD123]
J6  HDMI-TYPEA_SMD  [HDMI-TYPEA_SMD]
Q1  MMFTN3019E  [SOT523]
Q2  MMFTN3019E  [SOT523]
Q3  MMFTN3019E  [SOT523]
R28  4.7K  [R0402]
R29  20K  [R0402]
R30  100K  [R0402]
R31  10K  [R0402]
R32  1.8K  [R0402]
R33  10K  [R0402]
R34  1.8K  [R0402]
sheet P09. VO-LVDS
C48  10uF  [C0402]
C49  10uF  [C0402]
C50  10uF  [C0805]
C51  10uF  [C0805]
J7  FPC05-FDW-40P  [FPC05-40P]
R1230  0R  [R0402]
sheet P11. VI-Camera_MIPI_CSI
C62  NC/6.8pF  [C0402]
C63  10uF  [C0402]
C64  10uF  [C0402]
C67  10uF  [C0402]
C68  10uF  [C0402]
C72  10uF  [C0402]
C73  10uF  [C0402]
C394  NC/10pF  [C0402]
J10  FPC05-PUW-24P  [FPC05-24P]
Q8  MMFTN3019E  [SOT523]
Q9  MMFTN3019E  [SOT523]
R56  49.9K  [R0402]
R57  20K  [R0402]
R59  24.9K  [R0402]
R60  20K  [R0402]
R63  17.4K  [R0402]
R64  20K  [R0402]
R333  1.8K  [R0402]
R334  1.8K  [R0402]
R1221  22R  [R0402]
R1222  2.2K  [R0402]
R1223  2.2K  [R0402]
U7  ETA5050V0S2F  [SOT23-5]
U8  ETA5050V0S2F  [SOT23-5]
U9  ETA5050V0S2F  [SOT23-5]
sheet P17. 1MIC/2SPK/HP
C157  10uF  [C0402]
C158  10uF  [C0402]
C159  NC/100nF  [C0402]
C160  10uF  [C0402]
C161  10uF  [C0402]
C186  1uF  [C0402]
C187  100nF  [C0402]
C188  100nF  [C0402]
C192  1nF  [C0402]
C193  1nF  [C0402]
C194  1uF  [C0402]
C195  100nF  [C0402]
C196  100nF  [C0402]
C197  1nF  [C0402]
C198  1nF  [C0402]
C359  22uF  [C0603]
C360  22uF  [C0603]
C361  22uF  [C0603]
C362  22uF  [C0603]
C363  22uF  [C0603]
C365  100nF  [C0402]
C366  100nF  [C0402]
D37  PE0402N12G01B  [V0402]
D38  PE0402N12G01B  [V0402]
D39  PE0402N12G01B  [V0402]
D40  PE0402N12G01B  [V0402]
D41  PE0402N12G01B  [V0402]
J25  PH2.0-4A  [PH200-4A]
J34  PJ-316-6A  [PJ-316A-6A]
J45  MX1.25T-S-2A  [MX125T-S-2A]
L21  UPZ1608E101-3R0TF  [L0603]
L22  UPZ1608E101-3R0TF  [L0603]
L23  UPZ1608E101-3R0TF  [L0603]
L24  UPZ1608E101-3R0TF  [L0603]
R163  1K  [R0402]
R164  100K  [R0402]
R165  0R  [R0402]
R166  1K  [R0402]
R167  1K  [R0402]
R169  1K  [R0402]
R170  1K  [R0402]
R197  20K  [R0402]
R198  20K  [R0402]
R199  100K  [R0402]
R200  20K  [R0402]
R201  20K  [R0402]
R331  10K  [R0402]
R338  0R  [R0603]
TP3  TP100  [TP100]
TP4  TP100  [TP100]
U24  NS4150B  [MSOP-8]
U25  NS4150B  [MSOP-8]
sheet P19. GPIO
C185  10uF  [C0402]
D44  SE05NRC14GA  [DFN2510-10L]
D45  SE05NRC14GA  [DFN2510-10L]
J31  PHD2.0-2X5A  [PHD200-2X5A]
R193  2.2K  [R0402]
R194  2.2K  [R0402]
R195  NC/0R  [R0402]
R196  0R  [R0402]

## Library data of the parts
C1 = C-G-SMD: DSC1: ±20%; DSC2: 25V; DSC3: 440mΩ; DSC4: 2000H; DSC5: -55~105℃; DSC6: 6.3x5.7mm; DSC7: GVZ1E107M0606CNVC; DSC8: 贴片; ID: 2; Manufacture: 鸿瑞凯电子; Part Name: 贴片铝电解电容; Price: 0.54
C2 C3 C9 C17 = C-0402: DSC1: ±10%; DSC2: 50V; DSC3: X7R; ERP Number: 1010200128; ID: 61; Manufacture: 三星|国巨|村田; Part Name: 贴片电容; Part Number: C020102120061; Price: 0.05
C4 C5 C11 C12 = C-0805: DSC1: ±10%; DSC2: 25V; DSC3: X5R; ERP Number: 1010200144; ID: 74; Manufacture: 三星|国巨|村田; Part Name: 贴片电容; Part Number: C020102120074; Price: 0.09
C6 C13 = C-0402: DSC1: ±5%; DSC2: 50V; DSC3: C0G; ERP Number: 1010200152; ID: 40; Manufacture: 三星|国巨|村田; Part Name: 贴片电容; Part Number: C020102120040; Price: 0.01
C7 C8 C10 C14-C16 C18 C20-C25 C27 C28 C359-C363 C369 C370 = C-0603: DSC1: ±20%; DSC2: 10V; DSC3: X5R; ID: 83; Manufacture: 三星|国巨|村田; Part Name: 贴片电容; Part Number: C020107143899; Price: 0.18
C187 C188 C195 C196 C397 = C-0402: DSC1: ±10%; DSC2: 10V; DSC3: X7R; ERP Number: 1010200128; ID: 61; Manufacture: 三星|国巨|村田; Part Name: 贴片电容; Part Number: C020102120061; Price: 0.05
D1 = DI-XI-S: DSC1: 单向; DSC2: Vrwm=16V; DSC3: VBR=17.8V; DSC6: Ppp=600W; ID: 31; Manufacture: 硕凯; Part Name: TVS
F1 = FUSE-SMD1812: DSC1: 16V; DSC2: 2.6A; DSC3: SCF260-16-1812RB; ID: 7; Manufacture: 硕凯; Part Name: 自恢复保险丝; Part Number: C160102670007; Price: 0.3
J1 = J-DC-044A-2_5: DSC1: 通孔弯针，内径2mm，2.5A，24VDC; DSC2: 11.5*10.1*7.3mm; DSC3: 通孔弯针; DSC4: DC-044A-2.5A-2.0(星坤); DSC5: DC0044A（九龙熹）; ID: 3; Part Name: DC座; Part Number: J100103010003
J2 = J-H-4P: DSC1: 4p; DSC2: 2.0mm间距; DSC3: 通孔180度直针; DSC4: 米黄色胶壳 耐高温; DSC5: JLX-PH20-4A（九龙熹）; DSC6: X2016WV-04-46SN(星坤); ID: 13; Part Name: PH; Part Number: J020302820003
L1 L2 = L-IND: DSC1: ±20%; DSC2: Isat=6.1A; DSC3: Irms=4.3A; DSC4: 48mΩ; DSC5: 4.0*4.0*2.0mm; DSC6: WPN4020H2R2MT(顺络); DSC7: FHD4020S-2R2MT(长江微电); DSC8: ZCRH4020-2.2uH-M(宗成); ERP Number: 1010200404; ID: 20; Manufacture: 宗成|长江微电|顺络; Part Name: 功率电感; Part Number: C060202340020; Price: 0.38
L3 = L-IND: DSC1: ±20%; DSC2: Isat=3.6A; DSC3: Irms=3A; DSC4: 54mΩ; DSC5: 2.5*2.0*1.2mm; DSC6: WPN252012H1R0MT(顺络); DSC7: FHD252012S-1R0MT(长江微电); DSC8: ZCRH252012-1uH-M(宗成); ID: 52; Manufacture: 宗成|长江微电|顺络; Part Name: 功率电感
LED3 = D-LED-CT: DSC1: 黄色LED，侧贴，3.2*1.5*1.0mm Right Angle SMD VF=2V; DSC2: E6C1204UYAC1UDA(亿晶源); ID: 11; Part Name: LED; Part Number: C140202660007; Price: 0.12
Q1-Q3 Q8-Q10 = N-MOS-Q: DSC1: Vds=30V; DSC2: Id=100mA; DSC3: Vgs(th)=1.5V; DSC4: Vgs=±20V; DSC5: pd=150mW; ERP Number: 1010800011; ID: 4; Manufacture: 先科; Part Name: N-MOS; Part Number: C030202190004; Price: 0.1
R3 = R-0402: DSC1: ±1%; DSC2: 1/16W; Part Name: 贴片电阻; Part Number: C011002080976
R4 = R-0402: DSC1: ±1%; DSC2: 1/16W; Part Name: 贴片电阻; Part Number: C011002080979
R5 R18 R164 = R-0402: DSC1: ±5%; DSC2: 1/16W; ERP Number: 1010200103; ID: 353; Part Name: 贴片电阻; Part Number: C011002080353; Price: 0.01
R6 R11 R12 R14 R31 R33 R415 = R-0402: DSC1: ±1%; DSC2: 1/16W; ERP Number: 1010200140; ID: 856; Part Name: 贴片电阻; Part Number: C011002080856; Price: 0.01
R7 R20 = R-0402: DSC1: ±5%; DSC2: 1/16W; ERP Number: 1010200182; ID: 345; Part Name: 贴片电阻; Part Number: C011002080345; Price: 0.01
R8 R9 = R-0402: DSC1: ±1%; DSC2: 1/16W; ERP Number: 1010200333; ID: 889; Part Name: 贴片电阻; Part Number: C011002080889; Price: 0.01
R10 = R-0402: DSC1: ±1%; DSC2: 1/16W; ID: 933; Part Name: 贴片电阻; Part Number: C011002080933; Price: 0.01
R19 R28 R1227 = R-0402: DSC1: ±5%; DSC2: 1/16W; ERP Number: 1010200177; ID: 320; Part Name: 贴片电阻; Part Number: C011002080320; Price: 0.01
R500 = R-0402: DSC1: ±5%; DSC2: 1/16W; Part Name: 贴片电阻; Part Number: C011002080328
R1220 = R-0402: DSC1: ±5%; DSC2: 1/16W; Part Name: 贴片电阻; Part Number: C011002080320
U1 U2 = U-ETA1654FSG_0: DSC1: Vi=4.5-17V; DSC2: Vo=0.805-13.5V; DSC3: Io=4A; DSC4: Vfb=0.805V; DSC5: 0.97; DSC6: 600KHz; DSC7: 同步降压; ID: 44; Manufacture: ETA; Part Name: DCDC; Part Number: C070209233998; Solder: 量产
U3 = U-ETA3417S2F: DSC1: Vi=2.6-7.0V; DSC2: Vo=0.6-7.0V; DSC3: Io=2.5A; DSC4: Vfb=0.6V; DSC6: 3MHz; DSC7: 同步降压; DSC8: 替代料：TI的TLV62569DBVR/矽力杰SY8089AAAC; ID: 43; Manufacture: ETA; Part Name: DCDC; Part Number: C070205183984; Solder: 量产
U4 = U-SY6280AAC: DSC1: 低能耗电源开关; DSC2: 2.4-5.5V 2A; DSC3: 80mA; DSC4: -40~85℃; ID: 1; Manufacture: ETA; Part Name: 功率开关; Price: 0.42
C26 C29 C47 C186 C194 = C-0402: DSC1: ±10%; DSC2: 10V; DSC3: X5R; ERP Number: 1010200054; ID: 64; Manufacture: 三星|国巨|村田; Part Name: 贴片电容; Part Number: C020102120064; Price: 0.02
D2 = DI-TVS-D: DSC1: 双向; DSC2: Vrwm=6.0V; DSC3: VBR=6.67V; DSC4: Vc=10.3V; DSC5: Ipp=58.3A; DSC6: Ppp=200W; ID: 26; Manufacture: 硕凯; Part Name: TVS
D86 = DI-XI-S: DSC1: VR=30V; DSC2: IF=200mA; DSC3: VF=350mV/10mA; DSC4: IR=0.5uA; Manufacture: 乐山无线电; Part Name: 肖特基二级管; Part Number: C040202220002
Hole1-Hole4 = MH-NOE: DSC1: 顶层和底层焊盘直径=6mm; DSC2: 孔径3.7mm; DSC3: 8个过孔; ID: 33; Part Name: 镀锡(金)焊盘固定孔
M1 = SOM3566-239P_3
MARK1-MARK4 = MARK-FID10X20_0: Part Name: 光学MARK点
R16 = R-0402: DSC1: ±1%; DSC2: 1/16W; Part Name: 贴片电阻; Part Number: C011002080630
R17 = R-0402: DSC1: ±1%; DSC2: 1/16W; Part Name: 贴片电阻; Part Number: C011002080638
R231 R1222 R1223 = R-0402: DSC1: ±5%; DSC2: 1/16W; Part Name: 贴片电阻; Part Number: C011002080311
R232 = R-0402: DSC1: ±5%; DSC2: 1/16W; Part Name: 贴片电阻; Part Number: C011002080303
R165 R1231 = R-0402: DSC1: ±5%; DSC2: 1/16W; ERP Number: 1010200100; ID: 217; Part Name: 贴片电阻; Part Number: C011002080217; Price: 0.01
U28 = U-SGM803-SXN3L-TR: DSC1: Detection Voltage: 2.93V,Active Low Open Drain ouput 240mS, Iq=13uA; DSC2: SOT-23; DSC3: -40℃~+85℃; Manufacture: SGMICRO(圣邦微); Part Name: 复位芯片; Part Number: C110102550005
C34-C39 C159 C365 C366 = C-0402: DSC1: ±10%; DSC2: 10V; DSC3: X7R; ID: 60; Manufacture: 三星|国巨|村田; Part Name: 贴片电容; Part Number: C020102120060; Price: 0.01
C40 C41 C48 C49 C63 C64 C67 C68 C72 C73 C185 = C-0402: DSC1: ±20%; DSC2: 6.3V; DSC3: X5R; Manufacture: 三星|国巨|村田; Part Name: 贴片电容; Part Number: C020102120068
C42 C43 C50 C51 = C-0805: DSC1: ±10%; DSC2: 25V; DSC3: X5R; Manufacture: 三星|国巨|村田; Part Name: 贴片电容; Part Number: C020102120074
J5 = J-FPC-30P: DSC1: 30P; DSC2: 0.5mm间距; DSC3: 上接 抽拉式 卧贴; DSC4: H=2mm; DSC5: 镀锡; DSC6: X05B20U30T(星坤); Part Name: FPC座; Part Number: J030102870027
TP1 TP2 = TP-TEST: DSC1: 焊盘0.8mm; DSC2: 无孔; DSC3: 圆形; DSC4: 单面; Part Name: 测试点
D6 D7 D44 D45 = DI-ESD-SE05NRC14GA: DSC1: 双向; DSC2: Vdc=5V; DSC3: Vbr=8V; DSC4: Vc=20V; DSC5: Cj=0.4pF; ID: 8; Manufacture: 硕凯; Part Name: ESD; Part Number: C040504013981; Price: 0.15; Solder: 推荐
D8-D11 D37-D41 = DI-ESD: DSC1: 双向; DSC2: Vdc=12V; DSC4: Vc=40V; DSC5: Cj=0.05pF; ID: 1; Manufacture: 硕凯; Part Name: ESD; Part Number: C040504013980; Price: 0.06; Solder: 推荐
D12 D13 = DI-XI-S: DSC1: VR=40V; DSC2: IF=1A; DSC3: VF=600mV/1A; DSC4: IR=1mA; ID: 5; Manufacture: 长电; Part Name: 肖特基二级管; Part Number: C040202220005; Price: 0.13
J6 = J-HDMI-19P: DSC1: HDMI 19P母座SMD铜壳四脚 黑胶LCP 耐高温; DSC2: 15*11.8*6mm; DSC3: 贴片; DSC4: JLX-HDMI-002（九龙熹）; DSC5: A71-05H9-111N1（星坤）; ID: 7; Part Name: HDMI座; Part Number: J050302920001
R29 = R-0402: DSC1: ±1%; DSC2: 1/16W; ID: 904; Part Name: 贴片电阻; Part Number: C011002080904; Price: 0.01
R30 = R-0402: DSC1: ±1%; DSC2: 1/16W; ERP Number: 1010200137; ID: 976; Part Name: 贴片电阻; Part Number: C011002080976; Price: 0.01
R32 R34 R333 R334 = R-0402: DSC1: ±1%; DSC2: 1/16W; ID: 769; Part Name: 贴片电阻; Part Number: C011002080769; Price: 0.01
J7 = J-FPC-40P: DSC1: 40P; DSC2: 0.5mm间距; DSC3: 下接 翻盖 卧贴; DSC4: H=2mm; DSC5: 镀锡; DSC6: X05A20L40T(星坤); Part Name: FPC座; Part Number: J030102870088
R195 R196 R1230 = R-0402: DSC1: ±5%; DSC2: 1/16W; Part Name: 贴片电阻; Part Number: C011002080217
C62 = C-0402: DSC1: ±0.25PF; DSC2: 50V; DSC3: C0G; ERP Number: 1010200056; ID: 18; Manufacture: 三星|国巨|村田; Part Name: 贴片电容; Part Number: C020102120018; Price: 0.01
C394 = C-0402: DSC1: ±5%; DSC2: 50V; DSC3: C0G; Manufacture: 三星|国巨|村田; Part Name: 贴片电容; Part Number: C020102120021
J10 = J-FPC-24P: DSC1: 24P; DSC2: 0.5mm间距; DSC3: 上接 抽拉式 卧贴; DSC4: H=2mm; DSC5: 镀锡; DSC6: X05B20U24T(星坤); ID: 34; Part Name: FPC座; Part Number: J030102870021
R56 = R-0402: DSC1: ±1%; DSC2: 1/16W; ID: 938; Part Name: 贴片电阻; Part Number: C011002080938; Price: 0.01
R57 R60 R64 R197 R198 R200 R201 = R-0402: DSC1: ±5%; DSC2: 1/16W; ID: 335; Part Name: 贴片电阻; Part Number: C011002080335; Price: 0.01
R59 = R-0402: DSC1: ±1%; DSC2: 1/16W; ERP Number: 1010200327; ID: 900; Part Name: 贴片电阻; Part Number: C011002080900; Price: 0.01
R63 = R-0402: DSC1: ±1%; DSC2: 1/16W; ID: 882; Part Name: 贴片电阻; Part Number: C011002080882; Price: 0.01
R1221 = R-0402: DSC1: ±5%; DSC2: 1/16W; Part Name: 贴片电阻; Part Number: C011002080262
U7-U9 = U-ETA5050: DSC1: Vi=2.5-5.5V; DSC2: Vo=adj; DSC3: Io=500mA; DSC5: Iq=40uA; ID: 28; Manufacture: ETA; Part Name: LDO; Part Number: C070111104620; Solder: 推荐
C157 C158 C160 C161 = C-0402: DSC1: ±20%; DSC2: 6.3V; DSC3: X5R; ID: 68; Manufacture: 三星|国巨|村田; Part Name: 贴片电容; Part Number: C020102120068; Price: 0.04
C192 C193 C197 C198 = C-0402: DSC1: ±10%; DSC2: 50V; DSC3: X7R; ERP Number: 1010200084; ID: 54; Manufacture: 三星|国巨|村田; Part Name: 贴片电容; Part Number: C020102120054; Price: 0.01
J25 = J-H-4P_9: DSC1: 4p; DSC2: 2.0mm间距; DSC3: 通孔180度直针; DSC4: 米黄色胶壳 耐高温; DSC5: A2001WV-4P(CJT); ID: 13; Part Name: PH; Part Number: J020302820003
J34 = J-PJ-316A-6A_0: DSC1: 3.5mm贴片式耳机座 凸头 6P 单定位柱; DSC2: 14*6*4mm; DSC4: PJ-316A-6A(韩荣); DSC5: PJ-31160（九龙熹）; ID: 10; Part Name: 音频耳机座; Part Number: J050502940002
J45 = J-A-2P: DSC1: 2p; DSC2: 1.25mm间距; DSC3: 立贴; DSC4: 米黄色胶壳 耐高温; DSC5: JLX-1.25T-2AB(九龙熹); DSC6: X9821WVS-02-9TSN(星坤); Part Name: MX1.25T; Part Number: J020102800058
L21-L24 = FB-0603: DSC1: 100Ω@100MHz; DSC2: 3A; DSC3: DCR=30mΩ; DSC4: 电源线; ERP Number: 1010200207; ID: 5; Manufacture: 顺络; Part Name: 贴片磁珠; Part Number: C060502370005; Price: 0.03
R163 R166 R167 R169 R170 = R-0402: DSC1: ±5%; DSC2: 1/16W; ERP Number: 1010200104; ID: 303; Part Name: 贴片电阻; Part Number: C011002080303; Price: 0.01
R199 = R-0402: DSC1: ±5%; DSC2: 1/16W; Part Name: 贴片电阻; Part Number: C011002080353
R331 = R-0402: DSC1: ±5%; DSC2: 1/16W; ERP Number: 1010200096; ID: 328; Part Name: 贴片电阻; Part Number: C011002080328; Price: 0.01
R338 = R-0603: DSC1: ±1%; DSC2: 1/10W; Part Name: 贴片电阻; Part Number: C011002081182
TP3 TP4 = TP-TEST: DSC1: 焊盘1mm; DSC2: 无孔; DSC3: 圆形; DSC4: 单面; Part Name: 测试点
U24 U25 = U-NS4150B: DSC1: 1*3W @4Ω,3~5.2V，Class D; DSC3: -40~85℃; Manufacture: Nsiway(纳芯威); Part Name: 功放; Part Number: C150102670003
J31 = J-H-2X5P: DSC1: 2x5; DSC2: 2.0mm间距; DSC3: 双排 通孔180度直针; DSC4: 米黄色胶壳 耐高温; DSC5: A2006WV-2x5P(CJT); Part Name: PHD; Part Number: J020502840002
R193 R194 = R-0402: DSC1: ±5%; DSC2: 1/16W; ERP Number: 1010200170; ID: 311; Part Name: 贴片电阻; Part Number: C011002080311; Price: 0.01

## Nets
GND: C1.2 C4.1 C5.1 C7.1 C8.1 C9.1 C10.1 C11.1 C12.1 C14.1 C15.1 C16.1 C17.1 C18.1 C20.1 C21.1 C22.1 C23.1 C24.1 C25.1 C26.1 C27.1 C28.1 C29.1 C40.1 C41.1 C42.1 C43.1 C47.1 C48.1 C49.1 C50.1 C51.1 C62.1 C63.1 C64.1 C67.1 C68.1 C72.1 C73.1 C158.1 C159.1 C161.1 C185.1 C186.1 C188.1 C192.2 C193.2 C194.1 C196.1 C197.2 C198.2 C359.1 C360.1 C361.1 C362.1 C363.1 C369.1 C370.1 C397.1 D1.A D2.C(I/O1) D6.3 D6.8 D7.3 D7.8 D8.2(I/O1) D9.2(I/O1) D10.2(I/O1) D11.2(I/O1) D37.2(I/O1) D38.2(I/O1) D39.2(I/O1) D40.2(I/O1) D41.2(I/O1) D44.3 D44.8 D45.3 D45.8 J1.2 J1.3 J1.5(TH1) J1.6(TH2) J2.1 J2.2 J5.10 J5.11 J5.12 J5.13 J5.15 J5.16 J5.20 J5.23 J5.26 J5.29 J5.31 J5.32 J6.2 J6.5 J6.8 J6.11 J6.17 J6.20 J6.21 J6.22 J6.23 J7.10 J7.13 J7.16 J7.19 J7.22 J7.25 J7.28 J7.31 J7.32 J7.33 J7.41 J7.42 J10.10 J10.13 J10.16 J10.19 J10.22 J10.25 J10.26 J31.10 J45.2 J45.3 J45.4 M1.170(GND1) M1.176(GND2) M1.181(GND3) M1.186(GND4) M1.187(GND5) M1.188(GND6) M1.192(GND7) M1.197(GND8) M1.198(GND9) M1.199(GND10) M1.205(GND11) M1.211(GND12) M1.212(GND13) M1.213(GND14) M1.218(GND15) M1.223(GND16) M1.224(GND17) M1.229(GND18) M1.232(GND19) M1.233(GND20) M1.238(GND21) M1.239(GND22) Q10.2(SOURCE) R7.1 R8.1 R9.1 R12.1 R17.1 R20.1 R30.1 R57.1 R60.1 R64.1 R165.1 R199.1 R231.1 R331.2 R500.2 R1220.1 TP4.1 U1.3(GND) U2.3(GND) U3.2(GND) U4.2(GND) U7.2(GND) U8.2(GND) U9.2(GND) U24.7(GND) U25.7(GND) U28.1(GND) ; also on sheet 12 13 14 15 16 17 18 19
GND_EARTH: Hole1.1 ; also on sheet 15
VCC1V5_DVP: C73.2 C394.2 J10.3 R63.2 U9.5(VOUT)
VCC1V8_DVP: C68.2 J10.4 Q8.1(GATE) Q9.1(GATE) R59.2 R1222.2 R1223.2 U8.5(VOUT)
VCC2V8_DVP: C64.2 J10.1 J10.2 R56.2 U7.5(VOUT)
VCC3V3_SD_OUT: M1.38(VCC3V3_SD_OUT) ; also on sheet 18
VCC3V3_SYS: C21.2 C22.2 C23.2 L3.2 R10.2 U4.5(IN) ; also on sheet 13 14 19
VCC5V_HDMI_TX: C47.2 D13.C J6.18
VCC5V_SYS: C6.2 C7.2 C8.2 C10.2 C18.2 C20.2 C27.2 C28.2 C369.2 C370.2 D2.A(I/O2) L1.2 M1.171(VCC5V0_SYS_IN2) M1.172(VCC5V0_SYS_IN1) R3.2 R18.2 R232.2 R500.1 U3.4(VIN) ; also on sheet 14
VCC-AMP: C359.2 C360.2 C361.2 C362.2 R338.2 U24.6(VCC) U25.6(VCC)
VCC_1V8_OUT: M1.166(VCC_1V8_OUT) R6.1 R14.2 ; also on sheet 19
VCC_5V: C13.2 C14.2 C15.2 C16.2 C363.2 D12.A D13.A L2.2 Q1.1(GATE) R4.2 R195.1 R338.1 ; also on sheet 12 14 16 17
VCC_12V: C1.1 C4.2 C5.2 C9.2 C11.2 C12.2 C17.2 C42.2 C43.2 C50.2 C51.2 D1.C F1.2 J5.2 J5.3 J5.4 J5.5 J7.38 J7.39 J7.40 R5.1 U1.1(IN) U2.1(IN)
VCC_DCIN: F1.1 J1.4 J2.3 J2.4
VCCIO5_IN: C26.2 C29.2 M1.83(VCCIO6_IN) M1.84(VCCIO5_IN) M1.228(VCC_3V3_OUT)
VDD_3V3: C24.2 C25.2 C40.2 C41.2 C48.2 C49.2 C63.2 C67.2 C72.2 J5.18 J5.19 J7.2 J7.3 Q2.1(GATE) Q3.1(GATE) R19.1 R29.2 R31.1 R33.1 R163.1 R164.2 R170.2 R193.2 R194.2 R196.1 R333.1 R334.1 R415.1 R1230.1 U4.1(VOUT) U7.1(VIN) U8.1(VIN) U9.1(VIN) ; also on sheet 12 14 15 16 18
CAM_CLKOUT0_MIPI_CSI: C62.2 J10.9 R16.1 R17.2
CIF_SCL: J10.7 Q8.2(SOURCE) R1222.1
CIF_SDA: J10.8 Q9.2(SOURCE) R1223.1
COLOR_ENABLE: J5.6 TP2.1
EDP_HPDIN_M1: J5.14 M1.158(PWM3_IR/EDP_HPDIN_M1/MCU_JTAG_TMS/GPIO0_C2_d)
eDP_ON: J5.9 M1.94(VOP_BT1120_D6/ETH1_REFCLKO_25M_M0/SDMMC2_PWREN_M1/GPIO3_B0_d)
EDP_TX_AUXN: C34.2 M1.22(EDP_TX_AUXn)
EDP_TX_AUXN_: C34.1 J5.21
EDP_TX_AUXP: C35.2 M1.23(EDP_TX_AUXp)
EDP_TX_AUXP_: C35.1 J5.22
EDP_TX_D0N: C38.2 M1.30(EDP_TX_D0n)
EDP_TX_D0N_: C38.1 J5.25
EDP_TX_D0P: C39.2 M1.31(EDP_TX_D0p)
EDP_TX_D0P_: C39.1 J5.24
EDP_TX_D1N: C36.2 M1.28(EDP_TX_D1n)
EDP_TX_D1N_: C36.1 J5.28
EDP_TX_D1P: C37.2 M1.29(EDP_TX_D1p)
EDP_TX_D1P_: C37.1 J5.27
GMAC1_MCLKINOUT_M0: M1.79(PWM13_M0/GMAC1_MCLKINOUT_M0/UART3_RX_M1/PDM_SDI3_M2/GPIO3_C0_d) ; also on sheet 15
GMAC1_MDC_M0: M1.77(PWM14_M0/VOP_PWM_M1/GMAC1_MDC_M0/UART7_TX_M1/PDM_CLK1_M2/GPIO3_C4_d) ; also on sheet 15
GMAC1_MDIO_M0: M1.76(PWM15_IR_M0/SPDIF_TX_M1/GMAC1_MDIO_M0/UART7_RX_M1/I2S1_LRCK_RX_M2/GPIO3_C5_d) ; also on sheet 15
GMAC1_RSTn: M1.82(VOP_BT1120_D13/SPI1_MOSI_M1/PCIE20_PERSTn_M1/I2S1_SDO2_M2/GPIO3_C1_d) ; also on sheet 15
GMAC1_RXD0_M0: M1.92(PWM8_M0/VOP_BT1120_D7/GMAC1_RXD0_M0/UART4_RX_M1/GPIO3_B1_d) ; also on sheet 15
GMAC1_RXD1_M0: M1.93(PWM9_M0/VOP_BT1120_D8/GMAC1_RXD1_M0/UART4_TX_M1/GPIO3_B2_d) ; also on sheet 15
GMAC1_RXDV_CRS_M0: M1.88(VOP_BT1120_D9/I2C5_SCL_M0/GMAC1_RXDV_CRS_M0/PDM_SDI0_M2/GPIO3_B3_d) ; also on sheet 15
GMAC1_RXER_M0: M1.87(VOP_BT1120_D10/I2C5_SDA_M0/GMAC1_RXER_M0/PDM_SDI1_M2/GPIO3_B4_d) ; also on sheet 15
GMAC1_TXD0_M0: M1.86(PWM10_M0/VOP_BT1120_D11/I2C3_SCL_M1/GMAC1_TXD0_M0/GPIO3_B5_d) ; also on sheet 15
GMAC1_TXD1_M0: M1.85(PWM11_IR_M0/VOP_BT1120_D12/I2C3_SDA_M1/GMAC1_TXD1_M0/GPIO3_B6_d) ; also on sheet 15
GMAC1_TXEN_M0: M1.78(PWM12_M0/GMAC1_TXEN_M0/UART3_TX_M1/PDM_SDI2_M2/GPIO3_B7_d) ; also on sheet 15
GPIO0_A5_USB_OTG_PWREN: M1.215(SDMMC0_PWREN/SATA_MP_SWITCH/PCIE20_CLKREQn_M0/GPIO0_A5_d) ; also on sheet 17
GPIO0_A6_USB_OTG0_DET: M1.216(GPU_PWREN/SATA_CP_POD/GPIO0_A6_d) ; also on sheet 17
GPIO0_B0_u_TP_INT_L: M1.161(CLK32K_IN/CLK32K_OUT0/GPIO0_B0_u) ; also on sheet 14
GPIO0_C7_d_TP_RST_L: M1.154(PWM0_M1/HDMITX_CEC_M1/UART0_CTSn/GPIO0_C7_d) ; also on sheet 14
GPIO0_D3_CIF_PDN_L: J10.6 M1.217(GPIO0_D3_d)
GPIO2_B1_WIFI_REG_ON_H: M1.52(UART8_RTSn_M0/I2C4_SDA_M1/SDMMC1_PWREN/GPIO2_B1_d) ; also on sheet 19
GPIO2_B2_WIFI_WAKE_HOST_H: M1.53(UART8_CTSn_M0/I2C4_SCL_M1/SDMMC1_DET/GPIO2_B2_u) ; also on sheet 19
GPIO2_B7_BT_REG_ON_H: M1.225(UART6_RTSn_M0/SPI1_MOSI_M0/I2S2_SCLK_RX_M0/GPIO2_B7_d) ; also on sheet 19
GPIO2_C0_BT_WAKE_HOST_H: M1.182(UART6_CTSn_M0/SPI1_CS0_M0/I2S2_LRCK_RX_M0/GPIO2_C0_d) ; also on sheet 19
GPIO2_C1_HOST_WAKE_BT_H: M1.226(UART7_RTSn_M0/SPI2_CLK_M0/ETH0_REFCLKO_25M/I2S2_MCLK_M0/GPIO2_C1_d) ; also on sheet 19
GPIO2_C6_CIF_RST_L: J10.5 M1.43(UART8_RX_M0/SPI1_CS1_M0/CLK32K_OUT1/GPIO2_C6_d)
GPIO3_D6_SPK_CTRL_L: M1.75(CIF_D8/EBC_SDDO8/GMAC1_TXD2_M1/UART1_TX_M1/PDM_CLK0_M1/GPIO3_D6_d) R199.2 U24.1(CTRL) U25.1(CTRL)
GPIO3_D7_LVDS_ON: J7.36 M1.74(CIF_D9/EBC_SDDO9/GMAC1_TXD3_M1/UART1_RX_M1/PDM_SDI0_M1/GPIO3_D7_d)
GPIO4_A0_MIPI_TX1_RST_L: M1.72(CIF_D10/EBC_SDDO10/GMAC1_TXCLK_M1/PDM_CLK1_M1/GPIO4_A0_d) ; also on sheet 14
GPIO4_B0_USB_HOST1_PWREN_H: M1.58(CAM_CLKOUT1/EBC_SDCE2/GMAC1_RXD1_M1/SPI3_MISO_M0/I2S1_SDO1_M1/GPIO4_B0_d) ; also on sheet 17
GPIO4_B1_CIF_PWREN_H: M1.70(ISP_PRELIGHT_TRIG/EBC_SDCE3/GMAC1_RXDV_CRS_M1/I2S1_SDO2_M1/GPIO4_B1_d) R1221.1
GPIO4_B4_USB_FE_D4_PWREN_H: M1.68(ISP_FLASH_TRIGIN/I2C2_SDA_M1/EBC_GDSP/VOP_BT656_CLK_M1/GPIO4_B4_d) ; also on sheet 16
GPIO4_B5_HUB_XRSTJ: M1.67(I2C2_SCL_M1/EBC_SDSHR/I2S1_SDO3_M1/GPIO4_B5_d) ; also on sheet 16
GPIO4_B6_USB_FE_D2_PWREN_H: M1.59(CIF_HREF/EBC_SDLE/GMAC1_MDC_M1/UART1_RTSn_M1/I2S2_MCLK_M1/GPIO4_B6_d) ; also on sheet 16
GPIO4_B7_USB_FE_D3_PWREN_H: M1.64(CIF_VSYNC/EBC_SDOE/GMAC1_MDIO_M1/I2S2_SCLK_TX_M1/GPIO4_B7_d) ; also on sheet 16
GPIO4_C0_USB_HOST2_PWREN_H: M1.60(PWM11_IR_M1/CIF_CLKOUT/EBC_GDCLK/GPIO4_C0_d) ; also on sheet 16
GPIO4_C1_USB_FE_D1_PWREN_H: M1.66(CIF_CLKIN/EBC_SDCLK/GMAC1_MCLKINOUT_M1/UART1_CTSn_M1/I2S2_SCLK_RX_M1/GPIO4_C1_d) ; also on sheet 16
HDMI_TX_CEC_PORT: D9.1(I/O2) J6.13 Q1.3(DRAIN)
HDMI_TX_CLKN: D7.5 D7.6 J6.12 M1.139(HDMI_TX_CLKn)
HDMI_TX_CLKP: D7.4 D7.7 J6.10 M1.140(HDMI_TX_CLKp)
HDMI_TX_D0N: D7.2 D7.9 J6.9 M1.141(HDMI_TX_D0n)
HDMI_TX_D0P: D7.1 D7.10 J6.7 M1.142(HDMI_TX_D0p)
HDMI_TX_D1N: D6.5 D6.6 J6.6 M1.143(HDMI_TX_D1n)
HDMI_TX_D1P: D6.4 D6.7 J6.4 M1.144(HDMI_TX_D1p)
HDMI_TX_D2N: D6.2 D6.9 J6.3 M1.145(HDMI_TX_D2n)
HDMI_TX_D2P: D6.1 D6.10 J6.1 M1.146(HDMI_TX_D2p)
HDMI_TX_HPD_PORT: D8.1(I/O2) J6.19 R28.2 R30.2
HDMI_TX_HPDIN: M1.135(HDMI_TX_HPDIN) R28.1
HDMI_TXDDC_SCL_PORT: D10.1(I/O2) J6.15 Q2.3(DRAIN) R32.2
HDMI_TXDDC_SDA_PORT: D11.1(I/O2) J6.16 Q3.3(DRAIN) R34.2
HDMITX_CEC_M0: M1.138(HDMITX_CEC_M0/SPI3_CS1_M1/GPIO4_D1_u) Q1.2(SOURCE) R29.1
HDMITX_SCL: M1.137(HDMITX_SCL/I2C5_SCL_M1/GPIO4_C7_u) Q2.2(SOURCE) R31.2
HDMITX_SDA: M1.136(HDMITX_SDA/I2C5_SDA_M1/GPIO4_D0_u) Q3.2(SOURCE) R33.2
HP_DET_L: M1.89(VOP_BT1120_D5/GMAC1_RXCLK_M0/SDMMC2_DET_M1/GPIO3_A7_d) R166.1
HP_SNS: J34.4(GND) M1.8(HP_SNS) R165.2
HPL_OUT: C157.2 C187.1 M1.7(HPL_OUT)
HPL_OUT+: C157.1 D37.1(I/O2) J34.2(L) R331.1
HPR_OUT: C160.2 C195.1 M1.9(HPR_OUT)
HPR_OUT+: C160.1 D39.1(I/O2) J34.3(R)
I2C1_SCL_TP: M1.160(I2C1_SCL/MCU_JTAG_TDO/GPIO0_B3_u) ; also on sheet 14
I2C1_SDA_TP: M1.159(I2C1_SDA/PCIE20_BUTTONRSTn/MCU_JTAG_TCK/GPIO0_B4_u) ; also on sheet 14
I2C2_SCL_M0_RTC: M1.149(PWM1_M1/I2C2_SCL_M0/SPI0_CLK_M0/PCIE20_WAKEn_M0/GPIO0_B5_u) ; also on sheet 13
I2C2_SDA_M0_RTC: M1.147(PWM2_M1/I2C2_SDA_M0/SPI0_MOSI_M0/PCIE20_PERSTn_M0/GPIO0_B6_u) ; also on sheet 13
I2C3_SCL_M0_OUT: D45.5 D45.6 J31.8 M1.200(I2C3_SDA_M0/UART3_RX_M0/AUDIOPWM_LOUT_p/GPIO1_A0_u) R194.1
I2C3_SDA_M0_OUT: D45.4 D45.7 J31.6 M1.196(I2C3_SCL_M0/UART3_TX_M0/AUDIOPWM_LOUT_n/GPIO1_A1_u) R193.1
I2C4_SCL_M0_MIPI CSI: M1.65(I2C4_SCL_M0/EBC_GDOE/ETH1_REFCLKO_25M_M1/SPI3_CLK_M0/I2S2_SDO_M1/GPIO4_B3_d) Q8.3(DRAIN) R334.2
I2C4_SDA_M0_MIPI CSI: M1.63(I2C4_SDA_M0/EBC_VCOM/GMAC1_RXER_M1/SPI3_MOSI_M0/I2S2_SDI_M1/GPIO4_B2_d) Q9.3(DRAIN) R333.2
I2S2_LRCK_TX_M0_WIFI: M1.45(UART9_RTSn_M0/SPI2_MOSI_M0/I2S2_LRCK_TX_M0/GPIO2_C3_d) ; also on sheet 19
I2S2_SCLK_TX_M0_WIFI: M1.42(UART7_CTSn_M0/SPI2_MISO_M0/I2S2_SCLK_TX_M0/GPIO2_C2_d) ; also on sheet 19
I2S2_SDI_M0_WIFI: M1.41(UART8_TX_M0/SPI2_CS1_M0/I2S2_SDI_M0/GPIO2_C5_d) ; also on sheet 19
I2S2_SDO_M0_WIFI: M1.44(UART9_CTSn_M0/SPI2_CS0_M0/I2S2_SDO_M0/GPIO2_C4_d) ; also on sheet 19
LCD_Self_Test: J5.17 TP1.1
MIC_IN1: C365.1 D40.1(I/O2) J34.1(MIC) R169.1
MIC_IN2: C366.1 D41.1(I/O2) J45.1 R167.1 TP3.1
MIC_L_IN: C366.2 M1.10(MIC1p/MIC_L)
MIC_R_IN: C365.2 M1.11(MIC1n/MIC_R)
MIPI_CSI_RX_CLK0N: J10.17 M1.105(MIPI_CSI_RX_CLK0n)
MIPI_CSI_RX_CLK0P: J10.18 M1.106(MIPI_CSI_RX_CLK0p)
MIPI_CSI_RX_D0N: J10.11 M1.113(MIPI_CSI_RX_D0n)
MIPI_CSI_RX_D0P: J10.12 M1.114(MIPI_CSI_RX_D0p)
MIPI_CSI_RX_D1N: J10.14 M1.111(MIPI_CSI_RX_D1n)
MIPI_CSI_RX_D1P: J10.15 M1.112(MIPI_CSI_RX_D1p)
MIPI_CSI_RX_D2N: J10.20 M1.109(MIPI_CSI_RX_D2n)
MIPI_CSI_RX_D2P: J10.21 M1.110(MIPI_CSI_RX_D2p)
MIPI_CSI_RX_D3N: J10.23 M1.107(MIPI_CSI_RX_D3n)
MIPI_CSI_RX_D3P: J10.24 M1.108(MIPI_CSI_RX_D3p)
MIPI_DSI_TX0_CLKN/LVDS_TX0_CLKN: J7.17 M1.125(MIPI_DSI_TX0_CLKn/LVDS_TX0_CLKn)
MIPI_DSI_TX0_CLKP/LVDS_TX0_CLKP: J7.18 M1.126(MIPI_DSI_TX0_CLKp/LVDS_TX0_CLKp)
MIPI_DSI_TX0_D0N/LVDS_TX0_D0N: J7.8 M1.133(MIPI_DSI_TX0_D0n/LVDS_TX0_D0n)
MIPI_DSI_TX0_D0P/LVDS_TX0_D0P: J7.9 M1.134(MIPI_DSI_TX0_D0p/LVDS_TX0_D0p)
MIPI_DSI_TX0_D1N/LVDS_TX0_D1N: J7.11 M1.131(MIPI_DSI_TX0_D1n/LVDS_TX0_D1n)
MIPI_DSI_TX0_D1P/LVDS_TX0_D1P: J7.12 M1.132(MIPI_DSI_TX0_D1p/LVDS_TX0_D1p)
MIPI_DSI_TX0_D2N/LVDS_TX0_D2N: J7.14 M1.129(MIPI_DSI_TX0_D2n/LVDS_TX0_D2n)
MIPI_DSI_TX0_D2P/LVDS_TX0_D2P: J7.15 M1.130(MIPI_DSI_TX0_D2p/LVDS_TX0_D2p)
MIPI_DSI_TX0_D3N/LVDS_TX0_D3N: J7.20 M1.127(MIPI_DSI_TX0_D3n/LVDS_TX0_D3n)
MIPI_DSI_TX0_D3P/LVDS_TX0_D3P: J7.21 M1.128(MIPI_DSI_TX0_D3p/LVDS_TX0_D3p)
MIPI_DSI_TX1_CLKN: M1.115(MIPI_DSI_TX1_CLKn) ; also on sheet 14
MIPI_DSI_TX1_CLKP: M1.116(MIPI_DSI_TX1_CLKp) ; also on sheet 14
MIPI_DSI_TX1_D0N: M1.123(MIPI_DSI_TX1_D0n) ; also on sheet 14
MIPI_DSI_TX1_D0P: M1.124(MIPI_DSI_TX1_D0p) ; also on sheet 14
MIPI_DSI_TX1_D1N: M1.121(MIPI_DSI_TX1_D1n) ; also on sheet 14
MIPI_DSI_TX1_D1P: M1.122(MIPI_DSI_TX1_D1p) ; also on sheet 14
MIPI_DSI_TX1_D2N: M1.119(MIPI_DSI_TX1_D2n) ; also on sheet 14
MIPI_DSI_TX1_D2P: M1.120(MIPI_DSI_TX1_D2p) ; also on sheet 14
MIPI_DSI_TX1_D3N: M1.117(MIPI_DSI_TX1_D3n) ; also on sheet 14
MIPI_DSI_TX1_D3P: M1.118(MIPI_DSI_TX1_D3p) ; also on sheet 14
PMIC_32KHz_OUT_WIFI: M1.180(PMIC_32KOUT) ; also on sheet 19
PMIC_EXT_EN: M1.167(PMIC_EXT_EN) R11.1
PMIC_PWRON: M1.168(PMIC_PWRON) ; also on sheet 13
PMIC_VDC: D86.C M1.169(VDC) R18.1 R20.2
PWM0_M0_eDP: J5.8 M1.162(PWM0_M0/CPUAVS/GPIO0_B7_d)
PWM4_LVDS: J7.35 M1.155(PWM4/VOP_PWM_M0/MCU_JTAG_TRSTn/GPIO0_C3_d)
PWM5_MIPI: M1.150(PWM5/SPI0_CS1_M0/UART0_RTSn/GPIO0_C4_d) ; also on sheet 14
PWM6_OUT: D45.2 D45.9 J31.4 M1.148(PWM6/SPI0_MISO_M0/GPIO0_C5_d)
PWM7_IR: D45.1 D45.10 J31.2 M1.151(PWM7_IR/SPI0_CS0_M0/GPIO0_C6_d)
RESETn: M1.222(RESETn) R1231.2 ; also on sheet 13
SARADC_VIN0/RECOVERY: M1.164(SARADC_VIN0/RECOVERY) ; also on sheet 13
SARADC_VIN1: M1.231(SARADC_VIN1) ; also on sheet 13
SARADC_VIN2: M1.165(SARADC_VIN2) ; also on sheet 13
SDMMC0_CLK_SD: M1.37(SDMMC0_CLK/TEST_CLKOUT/UART5_TX_M0/GPIO2_A2_d) ; also on sheet 18
SDMMC0_CMD_SD: M1.33(PWM10_M1/SDMMC0_CMD/UART5_RX_M0/GPIO2_A1_u) ; also on sheet 18
SDMMC0_D0_SD: M1.35(PWM8_M1/SDMMC0_D0/UART2_TX_M1/UART6_TX_M1/GPIO1_D5_u) ; also on sheet 18
SDMMC0_D1_SD: M1.32(PWM9_M1/SDMMC0_D1/UART2_RX_M1/UART6_RX_M1/GPIO1_D6_u) ; also on sheet 18
SDMMC0_D2_SD: M1.36(SDMMC0_D2/ARM_JTAG_TCK/UART5_CTSn_M0/GPIO1_D7_u) ; also on sheet 18
SDMMC0_D3_SD: M1.34(SDMMC0_D3/ARM_JTAG_TMS/UART5_RTSn_M0/GPIO2_A0_u) ; also on sheet 18
SDMMC0_DET_L_SD: M1.163(SDMMC0_DET/SATA_CP_DET/GPIO0_A4_u) ; also on sheet 18
SDMMC1_CLK_WIFI: M1.49(UART9_TX_M0/SDMMC1_CLK/GPIO2_B0_d) ; also on sheet 19
SDMMC1_CMD_WIFI: M1.54(UART9_RX_M0/SDMMC1_CMD/GPIO2_A7_u) ; also on sheet 19
SDMMC1_D0_WIFI: M1.51(UART6_RX_M0/SDMMC1_D0/GPIO2_A3_u) ; also on sheet 19
SDMMC1_D1_WIFI: M1.50(UART6_TX_M0/SDMMC1_D1/GPIO2_A4_u) ; also on sheet 19
SDMMC1_D2_WIFI: M1.55(UART7_RX_M0/SDMMC1_D2/GPIO2_A5_u) ; also on sheet 19
SDMMC1_D3_WIFI: M1.48(UART7_TX_M0/SDMMC1_D3/GPIO2_A6_u) ; also on sheet 19
SPI3_CLK_M1_OUT: D44.1 D44.10 J31.1 M1.206(PWM14_M1/SPI3_CLK_M1/I2S3_MCLK_M1/GPIO4_C2_d)
SPI3_CS0_M1_OUT: D44.5 D44.6 J31.7 M1.201(PWM13_M1/SPI3_CS0_M1/SATA0_ACT_LED/UART9_RX_M1/I2S3_SDI_M1/GPIO4_C6_d)
SPI3_MISO_M1_OUT: D44.4 D44.7 J31.5 M1.202(PWM12_M1/SPI3_MISO_M1/SATA1_ACT_LED/UART9_TX_M1/I2S3_SDO_M1/GPIO4_C5_d)
SPI3_MOSI_M1_OUT: D44.2 D44.9 J31.3 M1.204(PWM15_IR_M1/SPI3_MOSI_M1/I2S3_SCLK_M1/GPIO4_C3_d)
SYS_LED_H: M1.69(ISP_FLASHTRIGOUT/EBC_SDCE0/GMAC1_TXEN_M1/SPI3_CS0_M0/I2S1_SCLK_RX_M1/GPIO4_A6_d) R415.2 R1227.1
UART0_RX: M1.157(PWM1_M0/GPUAVS/UART0_RX/GPIO0_C0_d) ; also on sheet 12
UART0_TX: M1.156(PWM2_M0/NPUAVS/UART0_TX/MCU_JTAG_TDI/GPIO0_C1_d) ; also on sheet 12
UART1_CTSn_M0_WIFI: M1.39(SPI1_MISO_M0/UART1_CTSn_M0/GPIO2_B6_u) ; also on sheet 19
UART1_RTSn_M0_WIFI: M1.40(SPI1_CLK_M0/UART1_RTSn_M0/GPIO2_B5_u) ; also on sheet 19
UART1_RX_M0_WIFI: M1.47(UART1_RX_M0/GPIO2_B3_u) ; also on sheet 19
UART1_TX_M0_WIFI: M1.46(UART1_TX_M0/GPIO2_B4_u) ; also on sheet 19
UART2_RX_M0_DEBUG: M1.153(UART2_RX_M0_DEBUG/GPIO0_D0_u) ; also on sheet 18
UART2_TX_M0_DEBUG: M1.152(UART2_TX_M0_DEBUG/GPIO0_D1_u) ; also on sheet 18
UART5_RX_M1: M1.80(VOP_BT1120_D15/SPI1_CLK_M1/UART5_RX_M1/I2S1_SCLK_RX_M2/GPIO3_C3_d) ; also on sheet 12
UART5_TX_M1: M1.81(VOP_BT1120_D14/SPI1_MISO_M1/UART5_TX_M1/I2S1_SDO3_M2/GPIO3_C2_d) ; also on sheet 12
UART7_RX_M2: M1.73(CIF_D13/EBC_SDDO13/GMAC1_RXCLK_M1/UART7_RX_M2/PDM_SDI3_M1/GPIO4_A3_d) ; also on sheet 12
UART7_TX_M2: M1.62(CIF_D12/EBC_SDDO12/GMAC1_RXD3_M1/UART7_TX_M2/PDM_SDI2_M1/GPIO4_A2_d) ; also on sheet 12
UART9_RX_M2: M1.71(CIF_D15/EBC_SDDO15/GMAC1_TXD1_M1/UART9_RX_M2/I2S2_LRCK_RX_M1/GPIO4_A5_d) ; also on sheet 12
UART9_TX_M2: M1.61(CIF_D14/EBC_SDDO14/GMAC1_TXD0_M1/UART9_TX_M2/I2S2_LRCK_TX_M1/GPIO4_A4_d) ; also on sheet 12
USB3_HOST1_DM: M1.16(USB_HOST1_DM) ; also on sheet 17
USB3_HOST1_DP: M1.17(USB_HOST1_DP) ; also on sheet 17
USB3_HOST1_SSRXN: M1.14(USB3_HOST1_SSRXn/SATA1_RXn) ; also on sheet 17
USB3_HOST1_SSRXP: M1.15(USB3_HOST1_SSRXp/SATA1_RXp) ; also on sheet 17
USB3_HOST1_SSTXN: M1.12(USB3_HOST1_SSTXn/SATA1_TXn) ; also on sheet 17
USB3_HOST1_SSTXP: M1.13(USB3_HOST1_SSTXp/SATA1_TXp) ; also on sheet 17
USB_HOST2_DM: M1.101(USB_HOST2_DM) ; also on sheet 16
USB_HOST2_DP: M1.102(USB_HOST2_DP) ; also on sheet 16
USB_HOST3_DM: M1.99(USB_HOST3_DM) ; also on sheet 16
USB_HOST3_DP: M1.100(USB_HOST3_DP) ; also on sheet 16
USB_OTG0_DM: M1.20(USB_OTG0_DM) ; also on sheet 17
USB_OTG0_DP: M1.21(USB_OTG0_DP) ; also on sheet 17
USB_OTG0_ID: M1.18(USB_OTG0_ID) ; also on sheet 17
USB_OTG0_VBUSDET: M1.19(USB_OTG0_VBUSDET) ; also on sheet 17
VOLN: C193.1 J25.4 L22.2
VOLP: C192.1 J25.3 L21.2
VORN: C198.1 J25.2 L24.2
VORP: C197.1 J25.1 L23.2
N19354508: C394.1 R63.1 R64.2 U9.4(ADJ)
N19356461: R56.1 R57.2 U7.4(ADJ)
N19357233: R59.1 R60.2 U8.4(ADJ)
N69227462: C397.2 R5.2 R7.2 U1.5(EN)
N69227513: C6.1 R3.1 R8.2 U1.6(FB)
N69227900: L3.1 U3.3(SW)
N69227918: R10.1 R12.2 U3.5(FB)
N69724413: R11.2 U3.1(EN)
N69966774: C2.1 L1.1 U1.2(LX)
N69967080: C2.2 U1.4(BS)
N70531034: D12.C R32.1 R34.1
N70572735: C185.2 J31.9 R195.2 R196.2
N70591036: R6.2 U2.5(EN)
N70591050: C3.1 L2.1 U2.2(LX)
N70591060: C13.1 R4.1 R9.2 U2.6(FB)
N70591176: C3.2 U2.4(BS)
N70626310: M1.57(CAM_CLKOUT0/EBC_SDCE1/GMAC1_RXD0_M1/SPI3_CS1_M0/I2S1_LRCK_RX_M1/GPIO4_A7_d) R16.2
N70648039: C159.2 D38.1(I/O2) J34.5(L-COM) R164.1 R166.2
N70649018: C161.2 R169.2 R170.1
N70649944: C158.2 R163.2 R167.2
N70663154: R14.1 U4.4(EN)
N70663167: R1220.2 U4.3(OCB)
N70672743: C186.2 U24.2(Bypass)
N70672808: C187.2 R197.1
N70672810: R197.2 U24.3(INP)
N70672945: C188.2 R198.1
N70672947: R198.2 U24.4(INN)
N70673300: L21.1 U24.8(Vop)
N70673587: L22.1 U24.5(VON)
N70674127: C194.2 U25.2(Bypass)
N70674131: C195.2 R200.1
N70674133: R200.2 U25.3(INP)
N70674155: C196.2 R201.1
N70674157: R201.2 U25.4(INN)
N70674204: L23.1 U25.8(Vop)
N70674215: L24.1 U25.5(VON)
N70854426: R1221.2 U7.3(EN) U8.3(EN) U9.3(EN)
N70857622: LED3.1(+) R19.2
N70857637: LED3.2(-) Q10.3(DRAIN)
N70857653: Q10.1(GATE) R1227.2
N70885563: J7.4 R1230.2
N70966122: R231.2 R232.1 U28.3(VCC)
N70966143: D86.A R1231.1 U28.2(RSET#)

Not connected (* = marked no-connect by the designer): Hole2 1; Hole3 1; Hole4 1; J1 1(NC)*; J5 1* 7* 30*; J6 14*; J7 1* 5* 6 7 23* 24* 26* 27* 29* 30* 34* 37*; J34 6(R-COM); LED3 3(E)*; M1 1(PCIE20_RXn/SATA2_RXn) 2(PCIE20_RXp/SATA2_RXp) 3(PCIE20_TXn/SATA2_TXn) 4(PCIE20_TXp/SATA2_TXp) 5(PCIE20_REFCLKn) 6(PCIE20_REFCLKp) 24(EDP_TX_D3n) 25(EDP_TX_D3p) 26(EDP_TX_D2n) 27(EDP_TX_D2p) 56(CIF_D11/EBC_SDDO11/GMAC1_RXD2_M1/PDM_SDI1_M1/GPIO4_A1_d) 90(VOP_BT1120_CLK/GMAC1_TXCLK_M0/I2S3_SDI_M0/SDMMC2_CLK_M1/GPIO3_A6_d) 91(VOP_BT1120_D4/GMAC1_RXD3_M0/I2S3_SDO_M0/SDMMC2_CMD_M1/GPIO3_A5_d) 95(VOP_BT1120_D3/GMAC1_RXD2_M0/I2S3_LRCK_M0/SDMMC2_D3_M1/GPIO3_A4_d) 96(VOP_BT1120_D2/GMAC1_TXD3_M0/I2S3_SCLK_M0/SDMMC2_D2_M1/GPIO3_A3_d) 97(VOP_BT1120_D1/GMAC1_TXD2_M0/I2S3_MCLK_M0/SDMMC2_D1_M1/GPIO3_A2_d) 98(VOP_BT1120_D0/SPI1_CS0_M1/SDMMC2_D0_M1/GPIO3_A1_d) 103(MIPI_CSI_RX_CLK1n) 104(MIPI_CSI_RX_CLK1p) 173(SPK_OUTP) 174(SPK_OUTN) 175(PMIC_SLEEP) 177(BATDIV) 178(SNSP) 179(SNSN) 183(FSPI_CLK/FLASH_ALE/GPIO1_D0_d) 184(FSPI_D0/FLASH_RDY/GPIO1_D1_u) 185(FSPI_D1/FLASH_RDn/GPIO1_D2_u) 189(FSPI_CS0n/FLASH_CS0n/GPIO1_D3_u) 190(FSPI_D3/FLASH_CS1n/GPIO1_D4_u) 191(I2S1_SDO3_M0/I2S1_SDI1_M0/PDM_SDI1_M0/PCIE20_PERSTn_M2/GPIO1_B2_d) 193(I2S1_SDO2_M0/I2S1_SDI2_M0/PDM_SDI2_M0/PCIE20_WAKEn_M2/GPIO1_B1_d) 194(I2S1_SDO1_M0/I2S1_SDI3_M0/PDM_SDI3_M0/PCIE20_CLKREQn_M2/GPIO1_B0_d) 195(I2S1_SCLK_RX_M0/UART4_RX_M0/PDM_CLK1_M0/SPDIF_TX_M0/GPIO1_A4_d) 203(EDP_HPDIN_M0/SATA2_ACT_LED/SPDIF_TX_M2/I2S3_LRCK_M1/GPIO4_C4_d) 207(CIF_D5/EBC_SDDO5/SDMMC2_CLK_M0/I2S1_SDI1_M1/VOP_BT656_D5_M1/GPIO3_D3_d) 208(CIF_D4/EBC_SDDO4/SDMMC2_CMD_M0/I2S1_SDI0_M1/VOP_BT656_D4_M1/GPIO3_D2_d) 209(CIF_D3/EBC_SDDO3/SDMMC2_D3_M0/I2S1_SDO0_M1/VOP_BT656_D3_M1/GPIO3_D1_d) 210(CIF_D1/EBC_SDDO1/SDMMC2_D1_M0/I2S1_SCLK_TX_M1/VOP_BT656_D1_M1/GPIO3_C7_d) 214(REFCLK_OUT/GPIO0_A0_d) 219(GPIO0_D4_d) 220(GPIO0_D5_d) 221(GPIO0_D6_d) 227(NC) 230(SARADC_VIN3) 234(CIF_D0/EBC_SDDO0/SDMMC2_D0_M0/I2S1_MCLK_M1/VOP_BT656_D0_M1/GPIO3_C6_d) 235(CIF_D2/EBC_SDDO2/SDMMC2_D2_M0/I2S1_LRCK_TX_M1/VOP_BT656_D2_M1/GPIO3_D0_d) 236(CIF_D6/EBC_SDDO6/SDMMC2_DET_M0/I2S1_SDI2_M1/VOP_BT656_D6_M1/GPIO3_D4_d) 237(CIF_D7/EBC_SDDO7/SDMMC2_PWREN_M0/I2S1_SDI3_M1/VOP_BT656_D7_M1/GPIO3_D5_d); MARK1 1(FID10X20); MARK2 1(FID10X20); MARK3 1(FID10X20); MARK4 1(FID10X20)

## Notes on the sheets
sheet 1
- Revision History
- Version
- Date
- Author
- Change Note
- Approved
- V1A
- 2023.09.27
- First edition
sheet 2
- RK3566 Ref Block Diagram
- HDMI2.0 TX
- Camera1
- 30P FPC
- Panel
- RJ-45
- I2C_HDMI
- HDMITX_CEC_M0
  HDMITX_SCL
  HDMITX_SDA
- TP
  I2C1
- I2C4_M0_RTC/MIPI CSI
- LVDS
- Giga PHY
- TP-4P
- 4 Lane MIPI DSI
- 4 Lane
- I2C2_M0_OUT
- I2C1_TP
- eDP
- TMDS
- Debug
  UART2
- UART2_M0_DEBUG
- PMUIO1
  PMUIO2
- MIPI
  DSI_TX0
  LVDS
  TX0
- MIPI
  DSI
  TX1
- MIPI
  CSI
  RX
- Micro
  SD Card
- Micro
  SD Card
- HDMI
  TX
- SDMMC2 x 4bit
- eDP_TX
- VCCIO5
- UART0
- TTL
  UART0
- UART3_M0
- TTL
  UART5
- USB
  HOST2
- PMUPLL
- I2S2
- WIFI/BT
- FE1.1
  HUB
- USB_HOST2
- VCCIO4
- SDMMC1
- AP6256
- UART1_M0
- USB3.0
  HOST
- SS
- USB_HOST3
- USB/
  SATA/
  PCIE
- Rockchip
- USB3_HOST1_SST/SSR
- USB2.0
  OTG
- USB_OTG0
- USB2.0
  OTG
- RK3566
- VCCIO1
- Quad A55
- VCCIO2
- VCCIO3
- PH
- 5V
- UART7_M2
- MAIN
  POWER
- DC/DC
- or
- UART9_M2
- VCCIO6
- RS232-1
- RS232 芯片
- I2C4_M0_RTC/MIPI CSI
- RK809-5
  PMIC+Codec
- VCCIO7
- SARADC_VIN
- RS232-2
- RS232 芯片
- SARADC
- 12V  Adapter
- SKP OUT
- MIC
- HP OUT
- RTC
  HYM8563
- HDMITX_CEC_M0
  HDMITX_SCL
  HDMITX_SDA
- I2C_HDMI
- 此I2C为MIPI CSI 和RTC共用
- Headphone
- Power Key
- 功放NS4150Bx2
- Speaker
- 4R@3W x 2
- Keys
sheet 3
- 上电时序：VCC_12V----VCC5V0_SYS----VCC_3V3----VDD_3V3/VCC_5V
- DCDC
- VCC3V3_SD
- 12V
- SOM3566
- Micro
  SD Card
- ETA1654
- VCC5V0_SYS
- DCDC
- 5V
- 5V
- ETA1654
- VCC_5V
- HDMI
- VCC_5V
- 常供电
- 待机断电
- USB
- DCDC
- Swtich
- ETA3417
- SY6280AAC
- VDD_3V3
- HDMI
- VCC_3V3
- VDD_3V3
- 3.3V
- 3.3V
- FE1.1
- SY7201ABC
- MIPI DSI TX1
- LDO
- FE1.1
- RTL8211F-CG
- ETA5050
- VCC1V2_DVP
- LDO
- Camera
- AP6256
- LVDS
- ETA5050
- VCC1V8_DVP
- LDO
- EDP
- ETA5050
- VCC2V8_DVP
sheet 4
- VDC
- 自动开机
sheet 5
- eDP_TX
- Diff 100ohm ± 10%
- Diff 100ohm ± 10%
- Diff 100ohm ± 10%
sheet 6
- TO SOM3566
- Diff 100ohm ± 10%
- Diff 100ohm ± 10%
- Diff 100ohm ± 10%
- Diff 100ohm ± 10%
- HDMI TX CEC
- HDMI TX HPD
- HDMI TX DDC
sheet 7
- LVDS_TX
sheet 8
- TO SOM3566
- MIPI_CSI 4lanes
sheet 10
- HP/MIC_IN
- TO SOM3566
- Speaker Output(Stereo)
- TO SOM3566
sheet 11
- LED
- DCIN 12V
- VCC5V_SYS
- VCC_5V
- 现配置实际电压为4.8V
- 现配置实际电压为5.08V
- EN>1.2V
- EN>1.2V
- Vout=0.8x(1+R1/R2)
- Vout=0.8x(1+R1/R2)
- VCC3V3_SYS
- VDD_3V3
- 常供电
- 待机时断电
- Imax:2.5A
- 核心板1.8V 使能
- EN>1.2V
- Vout=0.6x(1+R1/R2)
